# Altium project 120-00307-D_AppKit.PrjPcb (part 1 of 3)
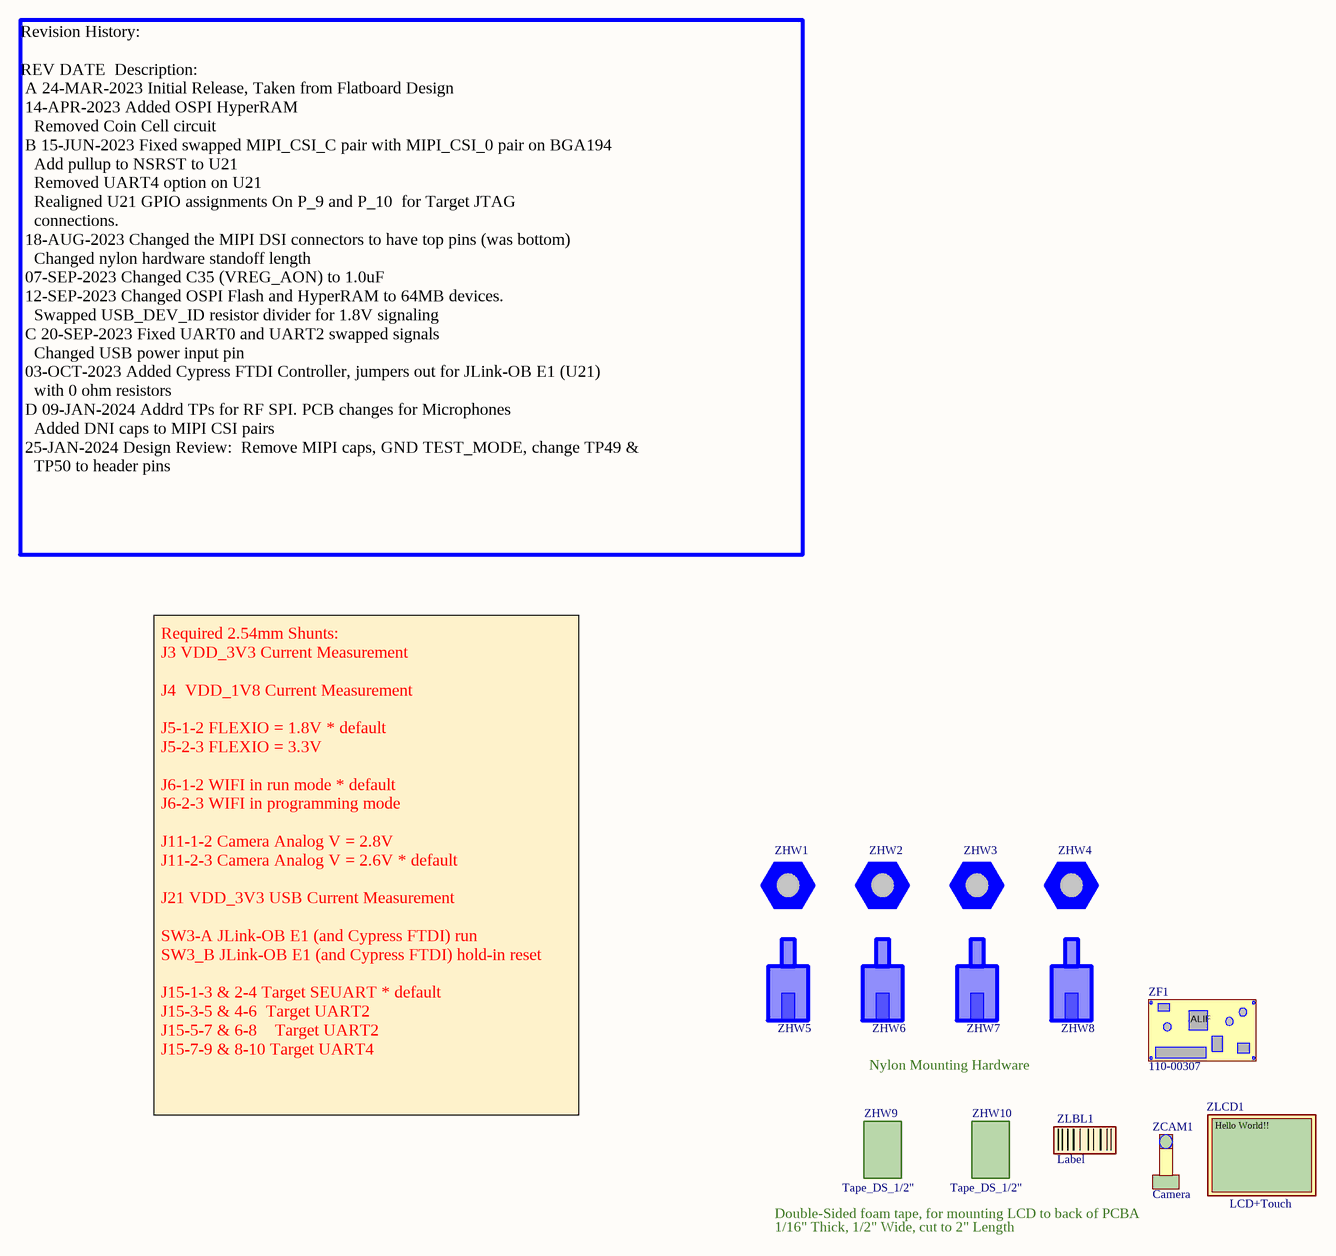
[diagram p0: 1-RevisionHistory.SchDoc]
ASSY_DWG_NO: 120-00307-D; CAGE_CODE: none; CheckedBy: n/a; CHK_APP_DATE: 1/9/24; DOC_NO_ASSY_DWG: 120-00307; DOC_NO_BOM: 250-00307; DOC_NO_FAB_DWG: 210-00307; DOC_NO_SCH_DWG: 220-00307; DOC_REV: D; DrawnBy: K Braun; DSN_APP_DATE: 09-JAN-24; ENG_APP_DATE: 01/09/24; Engineer: K Braun; Fab_DWG_NO: 110-00307; Name-Company: ALIF SEMICONDUCTOR; No-Fab: 110-00307; No-Rev: C; PCB_DWG_NO: 110-00307-D; PROJECT: 00307; Revision: D; SheetTotal: 12; title: APP KIT BOARD
14 sheets, 435 parts. Net scope: flat (ports and power ports of the same name join across sheets).
Board file: 120-00307-D_AppKit.PcbDoc
Sheets:
  1-RevisionHistory.SchDoc
  2-PowerInput.SchDoc
  3-CPUPower.SchDoc
  4-CPUMipiXoMemory.SchDoc
  5-WiFi.SchDoc
  6-GPIOTranslate.SchDoc
  7-CODEC.SchDoc
  8-Sensors.SchDoc
  9-MIPI_CSI.SchDoc
  10-MIPI_DSI.SchDoc
  11-CPU_GPIO.SchDoc
  12-JLINK_1.SchDoc
  13-JLINK_2.SchDoc
  14-CypressSEUART.SchDoc

## Sheet 1-RevisionHistory.SchDoc: APP KIT BOARD
size 431 x 279 mm; Organization: ORGANIZATION; Address1: ADDRESS 1; Address2: ADDRESS 2; Address3: ADDRESS 3; Address4: ADDRESS 4; DocumentNumber: 1; Revision: -; SheetNumber: 1; SheetTotal: 14; ENG_APP_DATE: --/--/--; DSN_APP_DATE: --/--/--; CHK_APP_DATE: --/--/--

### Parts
ZCAM1  Camera  (mechanical)
ZF1  110-00307  (mechanical)
ZHW1  #4-40  (value not drawn)  (mechanical)
ZHW2  #4-40  (value not drawn)  (mechanical)
ZHW3  #4-40  (value not drawn)  (mechanical)
ZHW4  #4-40  (value not drawn)  (mechanical)
ZHW5  #4-40 1/4"  (value not drawn)  (mechanical)
ZHW6  #4-40 1/4"  (value not drawn)  (mechanical)
ZHW7  #4-40 1/4"  (value not drawn)  (mechanical)
ZHW8  #4-40 1/4"  (value not drawn)  (mechanical)
ZHW9  Tape_DS_1/2"  (mechanical)
ZHW10  Tape_DS_1/2"  (mechanical)
ZLBL1  Label  (mechanical)
ZLCD1  LCD+Touch  (mechanical)

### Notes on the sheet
- Revision History:
  REV	DATE		Description:
  A	24-MAR-2023	Initial Release, Taken from Flatboard Design
  14-APR-2023	Added OSPI HyperRAM
  Removed Coin Cell circuit
  B	15-JUN-2023	Fixed swapped MIPI_CSI_C pair with MIPI_CSI_0 pair on BGA194
  Add pullup to NSRST to U21
  Removed UART4 option on U21
  Realigned U21 GPIO assignments On P_9 and P_10  for Target JTAG
  connections.
  18-AUG-2023	Changed the MIPI DSI connectors to have top pins (was bottom)
  Changed nylon hardware standoff length
  07-SEP-2023	Changed C35 (VREG_AON) to 1.0uF
  12-SEP-2023	Changed OSPI Flash and HyperRAM to 64MB devices.
  Swapped USB_DEV_ID resistor divider for 1.8V signaling
  C	20-SEP-2023	Fixed UART0 and UART2 swapped signals
  Changed USB power input pin
  03-OCT-2023	Added Cypress FTDI Controller, jumpers out for JLink-OB E1 (U21)
  with 0 ohm resistors
  D	09-JAN-2024	Addrd TPs for RF SPI. PCB changes for Microphones
  Added DNI caps to MIPI CSI pairs
  25-JAN-2024	Design Review:  Remove MIPI caps, GND TEST_MODE, change TP49 &
  TP50 to header pins
- Required 2.54mm Shunts:
  J3	VDD_3V3 Current Measurement
  J4 	VDD_1V8 Current Measurement
  J5-1-2	FLEXIO = 1.8V * default
  J5-2-3	FLEXIO = 3.3V
  J6-1-2	WIFI in run mode * default
  J6-2-3	WIFI in programming mode
  J11-1-2	Camera Analog V = 2.8V
  J11-2-3	Camera Analog V = 2.6V * default
  J21	VDD_3V3 USB Current Measurement
  SW3-A	JLink-OB E1 (and Cypress FTDI) run
  SW3_B	JLink-OB E1 (and Cypress FTDI) hold-in reset
  J15-1-3 & 2-4	Target SEUART * default
  J15-3-5 & 4-6 	Target UART2
  J15-5-7 & 6-8   	Target UART2
  J15-7-9 & 8-10	Target UART4
- Nylon Mounting Hardware
- Double-Sided foam tape, for mounting LCD to back of PCBA
- 1/16" Thick, 1/2" Wide, cut to 2" Length

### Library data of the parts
ZCAM1 = MOD_CAM: Module, Camera, 2 Lane MIPI; Manufacturer 1: AppleTec; Manufacturer Part Number 1: AP-VISION-ARX3A0-55-C
ZF1 = PCB_FAB: Printed Circuit Board  Fabrication; Manufacturer 1: Alif Semi; Manufacturer Part Number 1: 110-00307-D
ZHW1-ZHW4 = HW_NUT: Hardware, Standoff, Hex Female-Female, #4-40 x 1/4" H, 1/4" Dia, Nylon; Manufacturer 1: Essentra Comp; Manufacturer Part Number 1: 14HTSP001
ZHW5-ZHW8 = HW_STANDOFF_MF: Hardware, Standoff, Hex Male-Female, #4-40 x 5/8" H, 1/4" Dia, Nylon; Manufacturer 1: Keystone; Manufacturer Part Number 1: 4803
ZHW9 ZHW10 = HW_TAPE: Hardware, Tape, 2-sided Foam, 1/2 inch, 1/16 inch thick - Cut to 2 inch length; Manufacturer 1: 3M; Manufacturer Part Number 1: 7010379962
ZLBL1 = MOD_LABEL_GENERIC: Label, UPC, Agency and Lot Num, AppKit; Manufacturer 1: Alif; Manufacturer Part Number 1: -need a p/n-
ZLCD1 = MOD_LCD: Module, LCD, 2 Lane MIPI, 4.3 inch, 480x800,  w/ Touch Panel; Manufacturer 1: FocusLCD; Manufacturer Part Number 1: E43GB-I-MW405-C

## Sheet 2-PowerInput.SchDoc: APP KIT BOARD
size 431 x 279 mm; Organization: ORGANIZATION; Address1: ADDRESS 1; Address2: ADDRESS 2; Address3: ADDRESS 3; Address4: ADDRESS 4; DocumentNumber: 2; Revision: -; SheetNumber: 2; SheetTotal: 14; ENG_APP_DATE: --/--/--; DSN_APP_DATE: --/--/--; CHK_APP_DATE: --/--/--
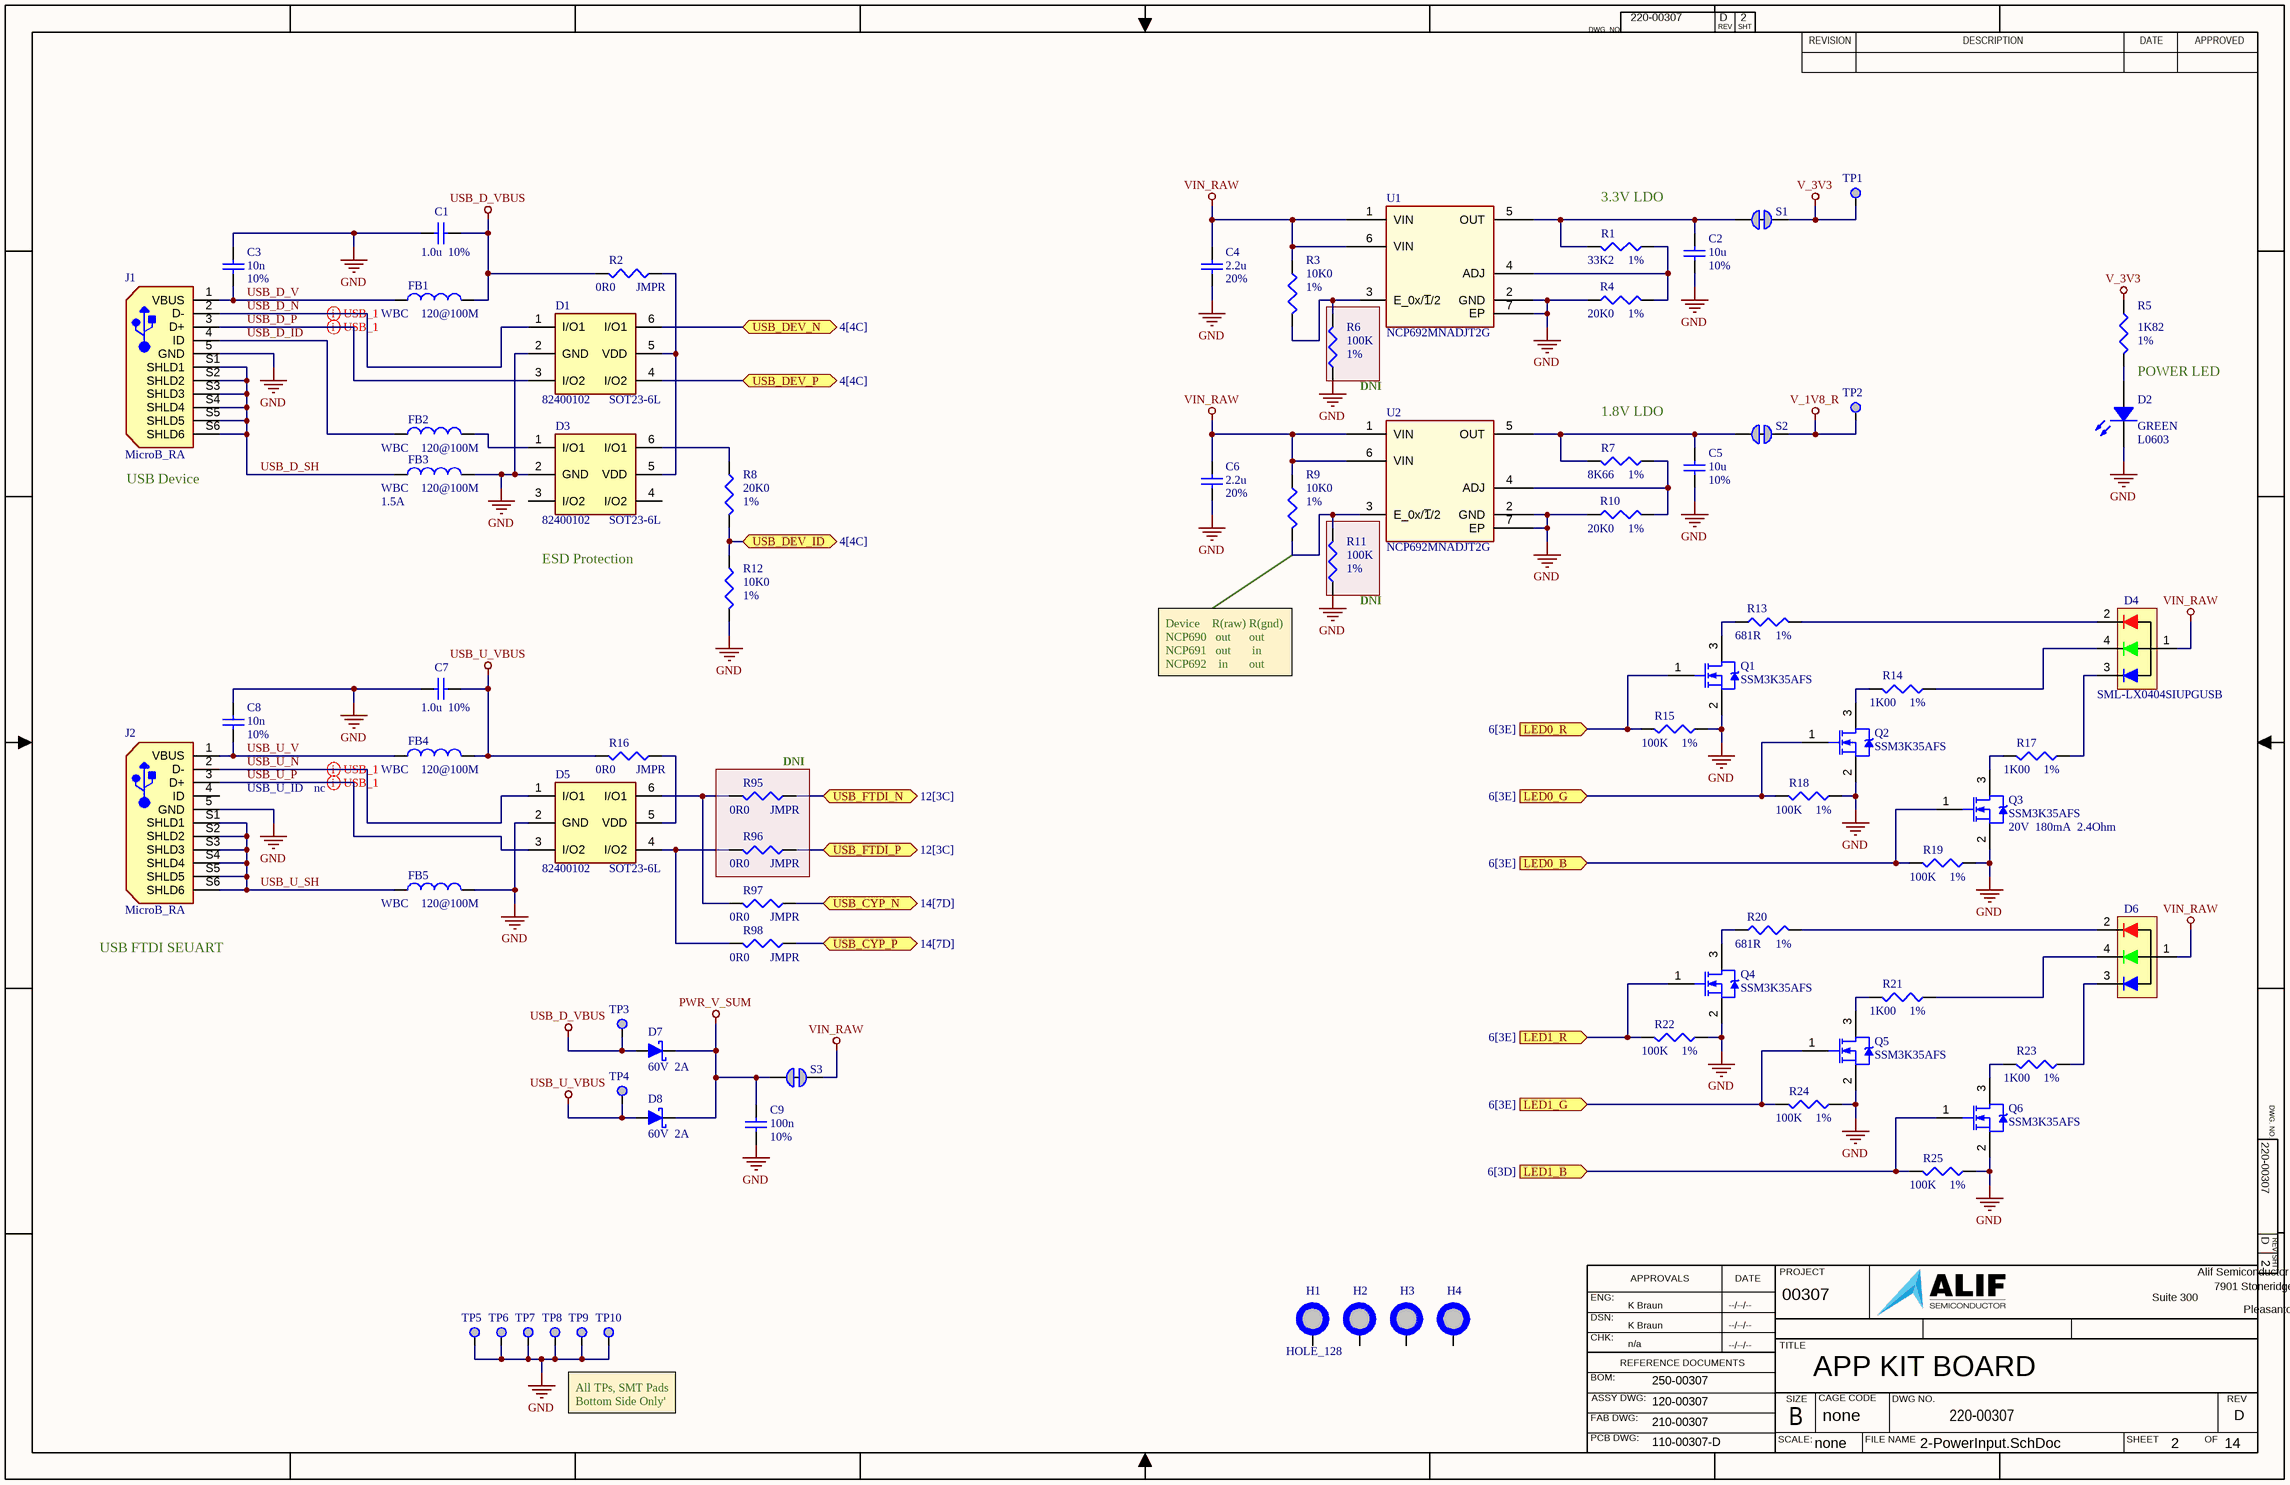
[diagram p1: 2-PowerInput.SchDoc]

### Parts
C1  value 1.0u  Tolerance: 10%  [CAPC0402-01]  (hidden comment: Cap)
C2  value 10u  Tolerance: 10%  [CAPC0402-01]  (hidden comment: Cap)
C3  value 10n  Tolerance: 10%  [CAPC0402-01]  (hidden comment: Cap)
C4  value 2.2u  Tolerance: 20%  [CAPC0402-01]  (hidden comment: Cap_225M25VX5R0402_1)
C5  value 10u  Tolerance: 10%  [CAPC0402-01]  (hidden comment: Cap)
C6  value 2.2u  Tolerance: 20%  [CAPC0402-01]  (hidden comment: Cap_225M25VX5R0402_1)
C7  value 1.0u  Tolerance: 10%  [CAPC0402-01]  (hidden comment: Cap)
C8  value 10n  Tolerance: 10%  [CAPC0402-01]  (hidden comment: Cap)
C9  value 100n  Tolerance: 10%  [CAPC0402-01]  (hidden comment: Cap)
D1  Size: SOT23-6L  [WE-TVS_SOT23-6L]  (hidden comment: TVS 5V 2pF)
D2  value GREEN  PackageReference: L0603  [LED_0603-GRN_AK]  (hidden comment: D LED2)
D3  Size: SOT23-6L  [WE-TVS_SOT23-6L]  (hidden comment: TVS 5V 2pF)
D4  SML-LX0404SIUPGUSB  [LED_SML-LX0404_LUM]
D5  Size: SOT23-6L  [WE-TVS_SOT23-6L]  (hidden comment: TVS 5V 2pF)
D6  SML-LX0404SIUPGUSB  [LED_SML-LX0404_LUM]  (value not drawn)
D7  value 60V  2A  [SOD123F_NXP]  (hidden comment: D Schottky)
D8  value 60V  2A  [SOD123F_NXP]  (hidden comment: D Schottky)
FB1  value WBC  Impedance: 120@100M  [FB_0402]  (hidden comment: Inductor)
FB2  value WBC  Impedance: 120@100M  [FB_0402]  (hidden comment: Inductor)
FB3  value WBC  Impedance: 120@100M  RMS_Current: 1.5A  [FB_0402]  (hidden comment: Inductor)
FB4  value WBC  Impedance: 120@100M  [FB_0402]  (hidden comment: Inductor)
FB5  value WBC  Impedance: 120@100M  [FB_0402]  (hidden comment: Inductor)
H1  HOLE_128  [Hole_#4]  (no BOM)
H2  HOLE_128  [Hole_#4]  (value not drawn)  (no BOM)
H3  HOLE_128  [Hole_#4]  (value not drawn)  (no BOM)
H4  HOLE_128  [Hole_#4]  (value not drawn)  (no BOM)
J1  value MicroB_RA  [AMPHENOL_10118194-0001LF]  (hidden comment: Conn_USB_MicroB_Rt_Angle)
J2  value MicroB_RA  [AMPHENOL_10118194-0001LF]  (hidden comment: Conn_USB_MicroB_Rt_Angle)
Q1  Manufacturer Part Number 1: SSM3K35AFS  [SC75_SSM_TOS-L]  (hidden comment: NMOS-2_SOT)
Q2  Manufacturer Part Number 1: SSM3K35AFS  [SC75_SSM_TOS-L]  (hidden comment: NMOS-2_SOT)
Q3  value 20V  180mA  2.4Ohm  Manufacturer Part Number 1: SSM3K35AFS  [SC75_SSM_TOS-L]  (hidden comment: NMOS-2_SOT)
Q4  Manufacturer Part Number 1: SSM3K35AFS  [SC75_SSM_TOS-L]  (hidden comment: NMOS-2_SOT)
Q5  Manufacturer Part Number 1: SSM3K35AFS  [SC75_SSM_TOS-L]  (hidden comment: NMOS-2_SOT)
Q6  Manufacturer Part Number 1: SSM3K35AFS  [SC75_SSM_TOS-L]  (hidden comment: NMOS-2_SOT)
R1  value 33K2  Tolerance: 1%  [RESC0402-01]  (hidden comment: Res3)
R2  value 0R0  Tolerance: JMPR  [RESC0402-01]  (hidden comment: Res3)
R3  value 10K0  Tolerance: 1%  [RESC0402-01]  (hidden comment: Res3)
R4  value 20K0  Tolerance: 1%  [RESC0402-01]  (hidden comment: Res3)
R5  value 1K82  Tolerance: 1%  [RESC0402-01]  (hidden comment: Res3)
R6  value 100K  Tolerance: 1%  [RESC0402-01]  (hidden comment: Res3)
R7  value 8K66  Tolerance: 1%  [RESC0402-01]  (hidden comment: Res3)
R8  value 20K0  Tolerance: 1%  [RESC0402-01]  (hidden comment: Res3)
R9  value 10K0  Tolerance: 1%  [RESC0402-01]  (hidden comment: Res3)
R10  value 20K0  Tolerance: 1%  [RESC0402-01]  (hidden comment: Res3)
R11  value 100K  Tolerance: 1%  [RESC0402-01]  (hidden comment: Res3)
R12  value 10K0  Tolerance: 1%  [RESC0402-01]  (hidden comment: Res3)
R13  value 681R  Tolerance: 1%  [RESC0402-01]  (hidden comment: Res3)
R14  value 1K00  Tolerance: 1%  [RESC0402-01]  (hidden comment: Res3)
R15  value 100K  Tolerance: 1%  [RESC0402-01]  (hidden comment: Res3)
R16  value 0R0  Tolerance: JMPR  [RESC0402-01]  (hidden comment: Res3)
R17  value 1K00  Tolerance: 1%  [RESC0402-01]  (hidden comment: Res3)
R18  value 100K  Tolerance: 1%  [RESC0402-01]  (hidden comment: Res3)
R19  value 100K  Tolerance: 1%  [RESC0402-01]  (hidden comment: Res3)
R20  value 681R  Tolerance: 1%  [RESC0402-01]  (hidden comment: Res3)
R21  value 1K00  Tolerance: 1%  [RESC0402-01]  (hidden comment: Res3)
R22  value 100K  Tolerance: 1%  [RESC0402-01]  (hidden comment: Res3)
R23  value 1K00  Tolerance: 1%  [RESC0402-01]  (hidden comment: Res3)
R24  value 100K  Tolerance: 1%  [RESC0402-01]  (hidden comment: Res3)
R25  value 100K  Tolerance: 1%  [RESC0402-01]  (hidden comment: Res3)
R95  value 0R0  Tolerance: JMPR  [RESC0402-01]  (hidden comment: Res3)
R96  value 0R0  Tolerance: JMPR  [RESC0402-01]  (hidden comment: Res3)
R97  value 0R0  Tolerance: JMPR  [RESC0402-01]  (hidden comment: Res3)
R98  value 0R0  Tolerance: JMPR  [RESC0402-01]  (hidden comment: Res3)
S1  SolderJumperShorted_Small  [Solderbridge_Shorted]  (value not drawn)  (net tie, no BOM)
S2  SolderJumperShorted_Small  [Solderbridge_Shorted]  (value not drawn)  (net tie, no BOM)
S3  SolderJumperShorted_Small  [Solderbridge_Shorted]  (value not drawn)  (net tie, no BOM)
TP1  TP_SMPAD  [TP_30_RND]  (value not drawn)  (no BOM)
TP2  TP_SMPAD  [TP_30_RND]  (value not drawn)  (no BOM)
TP3  TP_SMPAD  [TP_30_RND]  (value not drawn)  (no BOM)
TP4  TP_SMPAD  [TP_30_RND]  (value not drawn)  (no BOM)
TP5  TP_SMPAD  [TP_30_RND]  (value not drawn)  (no BOM)
TP6  TP_SMPAD  [TP_30_RND]  (value not drawn)  (no BOM)
TP7  TP_SMPAD  [TP_30_RND]  (value not drawn)  (no BOM)
TP8  TP_SMPAD  [TP_30_RND]  (value not drawn)  (no BOM)
TP9  TP_SMPAD  [TP_30_RND]  (value not drawn)  (no BOM)
TP10  TP_SMPAD  [TP_30_RND]  (value not drawn)  (no BOM)
U1  NCP692MNADJT2G  [DFN6_3X3_ONS]
U2  NCP692MNADJT2G  [DFN6_3X3_ONS]

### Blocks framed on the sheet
DNI: R95 R96

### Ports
LED0_B (in, see 6[3E]), LED0_G (in, see 6[3E]), LED0_R (in, see 6[3E]), LED1_B (in, see 6[3D]), LED1_G (in, see 6[3E]), LED1_R (in, see 6[3E]), USB_CYP_N (bidir, see 14[7D]), USB_CYP_P (bidir, see 14[7D]), USB_DEV_ID (bidir, see 4[4C]), USB_DEV_N (bidir, see 4[4C]), USB_DEV_P (bidir, see 4[4C]), USB_FTDI_N (bidir, see 12[3C]), USB_FTDI_P (bidir, see 12[3C])

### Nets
GND: C1.2 C2.1 C3.2 C4.1 C5.1 C6.1 C7.2 C8.2 C9.1 D1.2(GND) D2.K D3.2(GND) D5.2(GND) FB3.2 FB5.2 J1.5(GND) J2.5(GND) Q1.2(S) Q2.2(S) Q3.2(S) Q4.2(S) Q5.2(S) Q6.2(S) R4.1 R6.1 R10.1 R11.1 R12.2 R15.1 R18.1 R19.1 R22.1 R24.1 R25.1 TP5.1 TP6.1 TP7.1 TP8.1 TP9.1 TP10.1 U1.2(GND) U1.7(EP) U2.2(GND) U2.7(EP)
PWR_V_SUM: C9.2 D7.1(K) D8.1(K) S3.1
USB_D_VBUS: C1.1 D7.2(A) FB1.2 R2.2 TP3.1
USB_U_VBUS: C7.1 D8.2(A) FB4.2 R16.2 TP4.1
V_1V8_R: S2.2 TP2.1
V_3V3: R5.1 S1.2 TP1.1
VIN_RAW: C4.2 C6.2 D4.1(A) D6.1(A) R3.1 R9.1 S3.2 U1.1(VIN) U1.6(VIN) U2.1(VIN) U2.6(VIN)
P6_2: Q4.1(G) R22.2 ; port LED1_R
P6_5: Q5.1(G) R24.2 ; port LED1_G
P6_6: Q6.1(G) R25.2 ; port LED1_B
P7_4: Q2.1(G) R18.2 ; port LED0_G
P12_0: Q3.1(G) R19.2 ; port LED0_B
P12_3: Q1.1(G) R15.2 ; port LED0_R
USB_CYP_N: R97.1 ; port USB_CYP_N
USB_CYP_P: R98.1 ; port USB_CYP_P
USB_D_ID: FB2.1 J1.4(ID)
USB_D_N: D1.1(I/O1) J1.2(D-)
USB_D_P: D1.3(I/O2) J1.3(D+)
USB_D_SH: FB3.1 J1.S1(SHLD1) J1.S2(SHLD2) J1.S3(SHLD3) J1.S4(SHLD4) J1.S5(SHLD5) J1.S6(SHLD6)
USB_D_V: C3.1 FB1.1 J1.1(VBUS)
USB_DEV_N: D1.6(I/O1) ; port USB_DEV_N
USB_DEV_P: D1.4(I/O2) ; port USB_DEV_P
USB_FTDI_N: R95.1 ; port USB_FTDI_N
USB_FTDI_P: R96.1 ; port USB_FTDI_P
USB_ID: R8.2 R12.1 ; port USB_DEV_ID
USB_U_N: D5.1(I/O1) J2.2(D-)
USB_U_P: D5.3(I/O2) J2.3(D+)
USB_U_SH: FB5.1 J2.S1(SHLD1) J2.S2(SHLD2) J2.S3(SHLD3) J2.S4(SHLD4) J2.S5(SHLD5) J2.S6(SHLD6)
USB_U_V: C8.1 FB4.1 J2.1(VBUS)
NetC2_2: C2.2 R1.2 S1.1 U1.5(OUT)
NetC5_2: C5.2 R7.2 S2.1 U2.5(OUT)
NetD1_5: D1.5(VDD) D3.5(VDD) R2.1
NetD2_A: D2.A R5.2
NetD3_1: D3.1(I/O1) FB2.2
NetD3_6: D3.6(I/O1) R8.1
NetD4_2: D4.2(RK) R13.2
NetD4_3: D4.3(BK) R17.1
NetD4_4: D4.4(GK) R14.1
NetD5_4: D5.4(I/O2) R96.2 R98.2
NetD5_5: D5.5(VDD) R16.1
NetD5_6: D5.6(I/O1) R95.2 R97.2
NetD6_2: D6.2(RK) R20.2
NetD6_3: D6.3(BK) R23.1
NetD6_4: D6.4(GK) R21.1
NetQ1_3: Q1.3(D) R13.1
NetQ2_3: Q2.3(D) R14.2
NetQ3_3: Q3.3(D) R17.2
NetQ4_3: Q4.3(D) R20.1
NetQ5_3: Q5.3(D) R21.2
NetQ6_3: Q6.3(D) R23.2
NetR1_1: R1.1 R4.2 U1.4(ADJ)
NetR3_2: R3.2 R6.2 U1.3(E_0x/~{1}/2)
NetR7_1: R7.1 R10.2 U2.4(ADJ)
NetR9_2: R9.2 R11.2 U2.3(E_0x/~{1}/2)

Not connected (* = marked no-connect by the designer): D3 3(I/O2) 4(I/O2); H1 1; H2 1; H3 1; H4 1; J2 4(ID)

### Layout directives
differential pair; differential pair class USB_D: USB_D_N, USB_D_P
differential pair; differential pair class USB_U: USB_U_N, USB_U_P

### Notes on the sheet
- 3.3V LDO
- DNI
- 1.8V LDO
- (near R5) POWER LED
- (near J1) USB Device
- (near D3) ESD Protection
- (near R11) DNI
- (near R11) Device    R(raw) R(gnd)
  NCP690   out      out
  NCP691   out       in
  NCP692    in       out
- USB_U_ID
- nc
- (near J2) USB FTDI SEUART
- All TPs, SMT Pads
  Bottom Side Only'

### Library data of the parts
C1 C7 = Cap: Cap,1.0uF,20%,25V,X5R,0402; Manufacturer 1: TDK; Manufacturer Part Number 1: CGB2A1X5R1E105K033BC; PCB_Footprint: CC0402
C2 C5 = Cap: Cap,10uF,20%,10V,X5R,0402; Manufacturer 1: AVX; Manufacturer Part Number 1: 0402ZD106MAT2A; PCB_Footprint: CC0402
C3 C8 = Cap: Cap,10nF,10%,50V,X7R,0402; Manufacturer 1: TDK; Manufacturer Part Number 1: CGA2B3X7R1H103K050BE; PCB_Footprint: CC0402
C4 C6 = Cap_225M25VX5R0402_1: Cap,2.2uF,20%,25V,X5R,0402; Manufacturer 1: TDK; Manufacturer Part Number 1: C1005X5R1E225M050BC; PCB_Footprint: CC0402
C9 = Cap: Cap,100nF,10%,50V,X7R,0402; Manufacturer 1: TDK; Manufacturer Part Number 1: C1005X7R1H104K050BE; PCB_Footprint: CC0402
D1 D3 D5 = 82400102: Diode,TVS  – High Speed Series, SOT23-6L, 2+1 Channel, 5Vdc, 2pF; Manufacturer: Wurth Elektronik; Manufacturer 1: Wurth; Reverse Peak Pulse Current: 7A; Channel ESD Clamping Voltage: 10V; Channel Reverse Leakage Current: 1uA; ESD Air Discharge Capability: 15kV; ESD Contact Discharge Capability: 8kV; Polarity: Unidirectional; Reverse Breakdown Voltage: 6V
D2 = D LED2: Diode,LED,Green 573nm,300mcd @ 20mA,0603; Manufacturer 1: Wurth; Manufacturer Part Number 1: 150060VS86000
D4 D6 = D LED_RGB_CA_1MMc1MM: Diode,LED,RGB, (@2mA) -> R=10mcd & 1.75V, G = 50mcd & 2.75V, B = 20mcd & 2.95V, 0404(1mm x 1mm); Manufacturer 1: Lumex
D7 D8 = D Schottky: Diode,Schottky,2A,60V, <50uA@60V,SOD123F; Manufacturer 1: OnSemi; Manufacturer Part Number 1: SS26FL
FB1-FB5 = Inductor: Ind,WidebandChoke,1.5A,120ohm@100MHz,95mOhm,0402; Manufacturer 1: MuRata; Manufacturer Part Number 1: BLM15EG121SN1D; Code_IEC: 1005
H1-H4 = HOLE_128: Hole, #4,--not a BOM item--; PCB_Footprint: TP_PAD1
J1 J2 = Conn_USB-5-6SHLD: Conn,Micro USB B Type Receptacle,Right Angle; Manufacturer: Amphenol FCI; Manufacturer Part Number 1: 10118194-0001LF; Pitch: 0.65mm; Gender: RCP; Rad Hard: No
Q1 Q2 Q4-Q6 = NMOS-2_SOT: MOSFET,N-CH,20V,250mA,1.1Ohm,SOT-23; Manufacturer 1: Toshiba; Note: Pin 2 is electrically connected to pin 4.; Value: 20V  180mA  2.4Ohm
Q3 = NMOS-2_SOT: MOSFET,N-CH,20V,250mA,1.1Ohm,SOT-23; Manufacturer 1: Toshiba; Note: Pin 2 is electrically connected to pin 4.
R1 = Res3: Res,33K2,1%,100ppm,0402; Manufacturer 1: Stackpol; Manufacturer Part Number 1: RMCF0402FT33K2; Wattage: 63mW
R2 R16 R97 R98 = Res3: Res,0R ohm,Jumper,0402; Manufacturer 1: Stackpol; Manufacturer Part Number 1: RMCF0402ZT0R00; Wattage: 63mW
R3 R9 R12 = Res3: Res,10K0,1%,100ppm,0402; Manufacturer 1: Stackpol; Manufacturer Part Number 1: RMCF0402FT10K0; Wattage: 63mW
R4 R8 R10 = Res3: Res,20K0,1%,100ppm,0402; Manufacturer 1: Stackpol; Manufacturer Part Number 1: RMCF0402FT20K0; Wattage: 63mW
R5 = Res3: Res,1K82,1%,100ppm,0402; Manufacturer 1: Stackpol; Manufacturer Part Number 1: RMCF0402FT1K82; Wattage: 63mW
R6 R11 = Res3: DNI,Res,100K,1%,100ppm,0402; Manufacturer 1: Stackpol; Manufacturer Part Number 1: RMCF0402FT100K; Wattage: 63mW
R7 = Res3: Res,8K66,1%,100ppm,0402; Manufacturer 1: Stackpol; Manufacturer Part Number 1: RMCF0402FT8K66; Wattage: 63mW
R13 R20 = Res3: Res,681R,1%,100ppm,0402; Manufacturer 1: Stackpol; Manufacturer Part Number 1: RMCF0402FT681R; Wattage: 63mW
R14 R17 R21 R23 = Res3: Res,1K00,1%,100ppm,0402; Manufacturer 1: Stackpol; Manufacturer Part Number 1: RMCF0402FT1K; Wattage: 63mW
R15 R18 R19 R22 R24 R25 = Res3: Res,100K,1%,100ppm,0402; Manufacturer 1: Stackpol; Manufacturer Part Number 1: RMCF0402FT100K; Wattage: 63mW
R95 R96 = Res3: DNI,Res,0R ohm,Jumper,0402; Manufacturer 1: Stackpol; Manufacturer Part Number 1: RMCF0402ZT0R00; Wattage: 63mW
S1-S3 = SolderJumperShorted_Small: DNI,Solderable Jumper,Shorted; Wattage: 63mW; PCB_Footprint: SSHORTED
TP1-TP10 = TP_SMPAD: Test Point, SMT Pad,--not a BOM item--; PCB_Footprint: TP_PAD1
U1 U2 = IC_LDO_NCP690MNADJT2G: IC, LDO,Adj 1.25V - 5.5V,1.0A,+ Enable,DFN6; Manufacturer 1: OnSemi

## Sheet 3-CPUPower.SchDoc: APP KIT BOARD
size 431 x 279 mm; Organization: ORGANIZATION; Address1: ADDRESS 1; Address2: ADDRESS 2; Address3: ADDRESS 3; Address4: ADDRESS 4; DocumentNumber: 3; Revision: -; SheetNumber: 3; SheetTotal: 14; ENG_APP_DATE: --/--/--; DSN_APP_DATE: --/--/--; CHK_APP_DATE: --/--/--
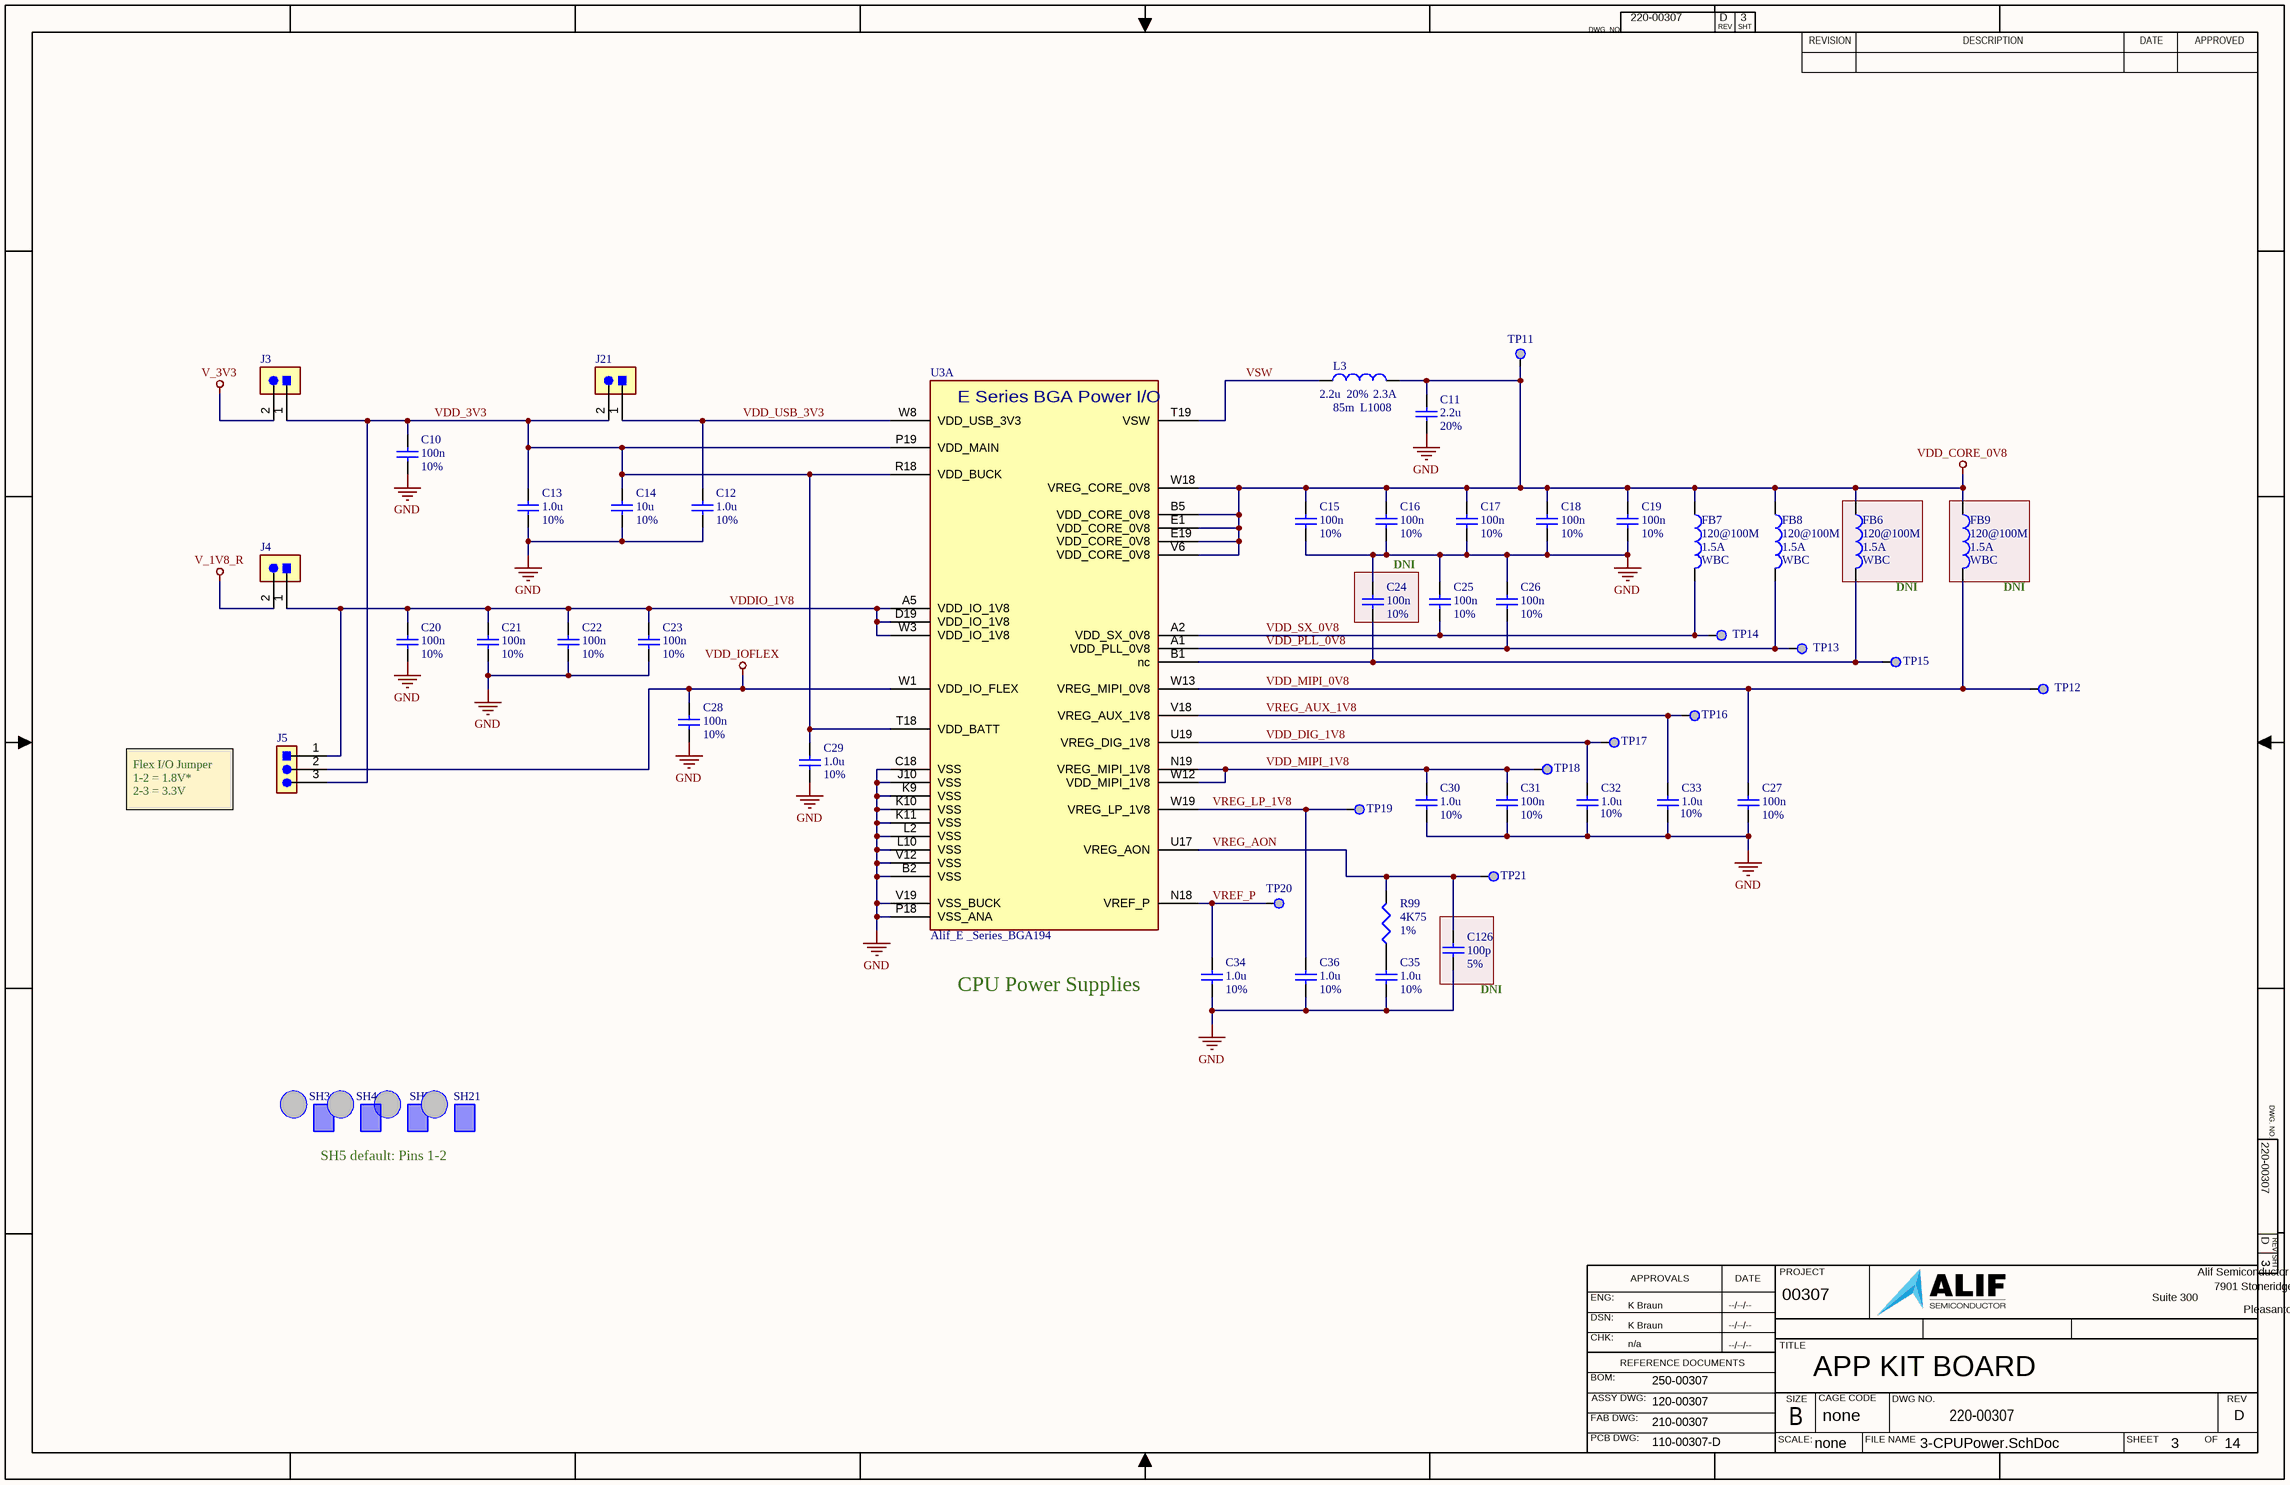
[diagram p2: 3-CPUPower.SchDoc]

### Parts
C10  value 100n  Tolerance: 10%  [CAPC0402-01]  (hidden comment: Cap)
C11  value 2.2u  Tolerance: 20%  [CAPC0402-01]  (hidden comment: Cap_225M25VX5R0402_1)
C12  value 1.0u  Tolerance: 10%  [CAPC0402-01]  (hidden comment: Cap)
C13  value 1.0u  Tolerance: 10%  [CAPC0402-01]  (hidden comment: Cap)
C14  value 10u  Tolerance: 10%  [CAPC0402-01]  (hidden comment: Cap)
C15  value 100n  Tolerance: 10%  [CAPC0402-01]  (hidden comment: Cap)
C16  value 100n  Tolerance: 10%  [CAPC0402-01]  (hidden comment: Cap)
C17  value 100n  Tolerance: 10%  [CAPC0402-01]  (hidden comment: Cap)
C18  value 100n  Tolerance: 10%  [CAPC0402-01]  (hidden comment: Cap)
C19  value 100n  Tolerance: 10%  [CAPC0402-01]  (hidden comment: Cap)
C20  value 100n  Tolerance: 10%  [CAPC0402-01]  (hidden comment: Cap)
C21  value 100n  Tolerance: 10%  [CAPC0402-01]  (hidden comment: Cap)
C22  value 100n  Tolerance: 10%  [CAPC0402-01]  (hidden comment: Cap)
C23  value 100n  Tolerance: 10%  [CAPC0402-01]  (hidden comment: Cap)
C24  value 100n  Tolerance: 10%  [CAPC0402-01]  (hidden comment: Cap)
C25  value 100n  Tolerance: 10%  [CAPC0402-01]  (hidden comment: Cap)
C26  value 100n  Tolerance: 10%  [CAPC0402-01]  (hidden comment: Cap)
C27  value 100n  Tolerance: 10%  [CAPC0402-01]  (hidden comment: Cap)
C28  value 100n  Tolerance: 10%  [CAPC0402-01]  (hidden comment: Cap)
C29  value 1.0u  Tolerance: 10%  [CAPC0402-01]  (hidden comment: Cap)
C30  value 1.0u  Tolerance: 10%  [CAPC0402-01]  (hidden comment: Cap)
C31  value 100n  Tolerance: 10%  [CAPC0402-01]  (hidden comment: Cap)
C32  value 1.0u  Tolerance: 10%  [CAPC0402-01]  (hidden comment: Cap)
C33  value 1.0u  Tolerance: 10%  [CAPC0402-01]  (hidden comment: Cap)
C34  value 1.0u  Tolerance: 10%  [CAPC0402-01]  (hidden comment: Cap)
C35  value 1.0u  Tolerance: 10%  [CAPC0402-01]  (hidden comment: Cap)
C36  value 1.0u  Tolerance: 10%  [CAPC0402-01]  (hidden comment: Cap)
C126  value 100p  Tolerance: 5%  [CAPC0402-01]  (hidden comment: Cap)
FB6  value WBC  Impedance: 120@100M  RMS_Current: 1.5A  [FB_0402]  (hidden comment: Inductor)
FB7  value WBC  Impedance: 120@100M  RMS_Current: 1.5A  [FB_0402]  (hidden comment: Inductor)
FB8  value WBC  Impedance: 120@100M  RMS_Current: 1.5A  [FB_0402]  (hidden comment: Inductor)
FB9  value WBC  Impedance: 120@100M  RMS_Current: 1.5A  [FB_0402]  (hidden comment: Inductor)
J3  TSW-102-07-G-S  [CONN_77311-146-02LF_AMP_HDR_1x2_2.5MM_STRT]  (value not drawn)
J4  TSW-102-07-G-S  [CONN_77311-146-02LF_AMP_HDR_1x2_2.5MM_STRT]  (value not drawn)
J5  TSW-103-07-G-S  [CONN_HDR_1X3_STRT_0.100]  (value not drawn)
J21  TSW-102-07-G-S  [CONN_77311-146-02LF_AMP_HDR_1x2_2.5MM_STRT]  (value not drawn)
L3  value 2.2u  PackageReference: L1008  DCR: 85m  RMS_Current: 2.3A  Tolerance: 20%  [INDC2520X120N]  (hidden comment: Inductor)
R99  value 4K75  Tolerance: 1%  [RESC0402-01]  (hidden comment: Res3)
SH3  Shunt  (value not drawn)  (mechanical)
SH4  Shunt  (value not drawn)  (mechanical)
SH5  Shunt  (value not drawn)  (mechanical)
SH21  Shunt  (value not drawn)  (mechanical)
TP11  TP_SMPAD  [TP_30_RND]  (value not drawn)  (no BOM)
TP12  TP_SMPAD  [TP_30_RND]  (value not drawn)  (no BOM)
TP13  TP_SMPAD  [TP_30_RND]  (value not drawn)  (no BOM)
TP14  TP_SMPAD  [TP_30_RND]  (value not drawn)  (no BOM)
TP15  TP_SMPAD  [TP_30_RND]  (value not drawn)  (no BOM)
TP16  TP_SMPAD  [TP_30_RND]  (value not drawn)  (no BOM)
TP17  TP_SMPAD  [TP_30_RND]  (value not drawn)  (no BOM)
TP18  TP_SMPAD  [TP_30_RND]  (value not drawn)  (no BOM)
TP19  TP_SMPAD  [TP_30_RND]  (value not drawn)  (no BOM)
TP20  TP_SMPAD  [TP_30_RND]  (value not drawn)  (no BOM)
TP21  TP_SMPAD  [TP_30_RND]  (value not drawn)  (no BOM)
U3  Alif_E _Series_BGA194  [BGA194 _CENTERED]  (part A of 4)

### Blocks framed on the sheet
DNI: C24

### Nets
GND: C10.1 C11.1 C12.1 C13.1 C14.1 C15.1 C16.1 C17.1 C18.1 C19.1 C20.1 C21.1 C22.1 C23.1 C24.2 C25.2 C26.2 C27.1 C28.1 C29.1 C30.1 C31.1 C32.1 C33.1 C34.1 C35.1 C36.1 C126.1 U3.B2(VSS) U3.C18(VSS) U3.J10(VSS) U3.K9(VSS) U3.K10(VSS) U3.K11(VSS) U3.L2(VSS) U3.L10(VSS) U3.P18(VSS_ANA) U3.V12(VSS) U3.V19(VSS_BUCK)
V_1V8_R: J4.2
V_3V3: J3.2
VDD_CORE_0V8: C11.2 C15.2 C16.2 C17.2 C18.2 C19.2 FB6.1 FB7.1 FB8.1 FB9.1 L3.2 TP11.1 U3.B5(VDD_CORE_0V8) U3.E1(VDD_CORE_0V8) U3.E19(VDD_CORE_0V8) U3.V6(VDD_CORE_0V8) U3.W18(VREG_CORE_0V8)
VDD_IOFLEX: C28.2 J5.2 U3.W1(VDD_IO_FLEX)
VDD_3V3: C10.2 C13.2 C14.2 C29.2 J3.1 J5.3 J21.2 U3.P19(VDD_MAIN) U3.R18(VDD_BUCK) U3.T18(VDD_BATT)
VDD_DIG_1V8: C32.2 TP17.1 U3.U19(VREG_DIG_1V8)
VDD_MIPI_0V8: C27.2 FB9.2 TP12.1 U3.W13(VREG_MIPI_0V8)
VDD_MIPI_1V8: C30.2 C31.2 TP18.1 U3.N19(VREG_MIPI_1V8) U3.W12(VDD_MIPI_1V8)
VDD_PLL_0V8: C26.1 FB8.2 TP13.1 U3.A1(VDD_PLL_0V8)
VDD_SX_0V8: C25.1 FB7.2 TP14.1 U3.A2(VDD_SX_0V8)
VDD_USB_3V3: C12.2 J21.1 U3.W8(VDD_USB_3V3)
VDDIO_1V8: C20.2 C21.2 C22.2 C23.2 J4.1 J5.1 U3.A5(VDD_IO_1V8) U3.D19(VDD_IO_1V8) U3.W3(VDD_IO_1V8)
VREF_P: C34.2 TP20.1 U3.N18(VREF_P)
VREG_AON: C126.2 R99.2 TP21.1 U3.U17(VREG_AON)
VREG_AUX_1V8: C33.2 TP16.1 U3.V18(VREG_AUX_1V8)
VREG_LP_1V8: C36.2 TP19.1 U3.W19(VREG_LP_1V8)
VSW: L3.1 U3.T19(VSW)
NetC24_1: C24.1 FB6.2 TP15.1 U3.B1(nc)
NetC35_2: C35.2 R99.1

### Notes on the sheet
- DNI
- (near FB9) DNI
- Flex I/O Jumper
  1-2 = 1.8V*
  2-3 = 3.3V
- CPU Power Supplies
- (near C126) DNI
- SH5 default: Pins 1-2

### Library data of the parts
C10 C15-C23 C25-C28 C31 = Cap: as C9 on sheet 2-PowerInput
C11 = Cap_225M25VX5R0402_1: as C4 on sheet 2-PowerInput
C12 C13 C29 C30 C32-C36 = Cap: as C1 on sheet 2-PowerInput
C14 = Cap: as C2 on sheet 2-PowerInput
C24 = Cap: DNI, Cap,100nF,10%,50V,X7R,0402; Manufacturer 1: TDK; Manufacturer Part Number 1: C1005X7R1H104K050BE; PCB_Footprint: CC0402
C126 = Cap_SMT: DNI,Cap,100pF,5%,50V,C0G,0402; Manufacturer 1: Kemet; Manufacturer Part Number 1: CBR04C101J3GAC; PCB_Footprint: CC0402
FB6 FB9 = Inductor: DNI, Ind,WidebandChoke,1.5A,120ohm@100MHz,95mOhm,0402; Manufacturer 1: MuRata; Manufacturer Part Number 1: BLM15EG121SN1D; Code_IEC: 1005
FB7 FB8 = Inductor: as FB1 on sheet 2-PowerInput
J3 J4 J21 = Hdr_M_1X2_2M54_STRT_UNSHROUD: Hdr, 0.025" SQ Post Header, Through-hole, Vertical, -55 to 125 degC, 2.54 mm Pitch, 2-Pin, Male, RoHS; Manufacturer: Samtec; Manufacturer Part Number 1: TSW-102-07-L-S; Pitch: 2.54 mm
J5 = Hdr_M_1X3_2M54_STRT_UNSHROUD: Hdr, 0.025" SQ Post Header, Through-hole, Vertical, -55 to 125 degC, 2.54 mm Pitch, 3-Pin, Male, RoHS; Manufacturer: Samtec; Manufacturer Part Number 1: TSW-103-07-L-S; Pitch: 2.54 mm
L3 = Inductor: Ind,Unshielded,2.2uH,20%,2.3A,85mOhm,1008(2520); Manufacturer 1: MuRata; Manufacturer Part Number 1: DFE252012F-2R2M=P2; Code_IEC: 2520
R99 = Res3: Res,4K75,1%,100ppm,0402; Manufacturer 1: Stackpol; Manufacturer Part Number 1: RMCF0402FT4K75; Wattage: 63mW
SH3-SH5 SH21 = SHUNT_F_1x2_2.5MM_STRT: Shunt,Female,1x2,2.54mm,Gold,Strt; Manufacturer 1: Samtec; Manufacturer Part Number 1: SNT-100-BK-H
TP11-TP21 = TP_SMPAD: as TP1 on sheet 2-PowerInput
U3 = E7_B0_194BGA: IC,Alif E7 MCU, Rev B silicon, 5.5MB MRAM, 13.5MB SRAM, BGA194; Manufacturer 1: Alif Semi; Manufacturer Part Number 1: AE722F80F55D5LS

## Sheet 4-CPUMipiXoMemory.SchDoc: APP KIT BOARD
size 431 x 279 mm; Organization: ORGANIZATION; Address1: ADDRESS 1; Address2: ADDRESS 2; Address3: ADDRESS 3; Address4: ADDRESS 4; DocumentNumber: 4; Revision: -; SheetNumber: 4; SheetTotal: 14; ENG_APP_DATE: --/--/--; DSN_APP_DATE: --/--/--; CHK_APP_DATE: --/--/--
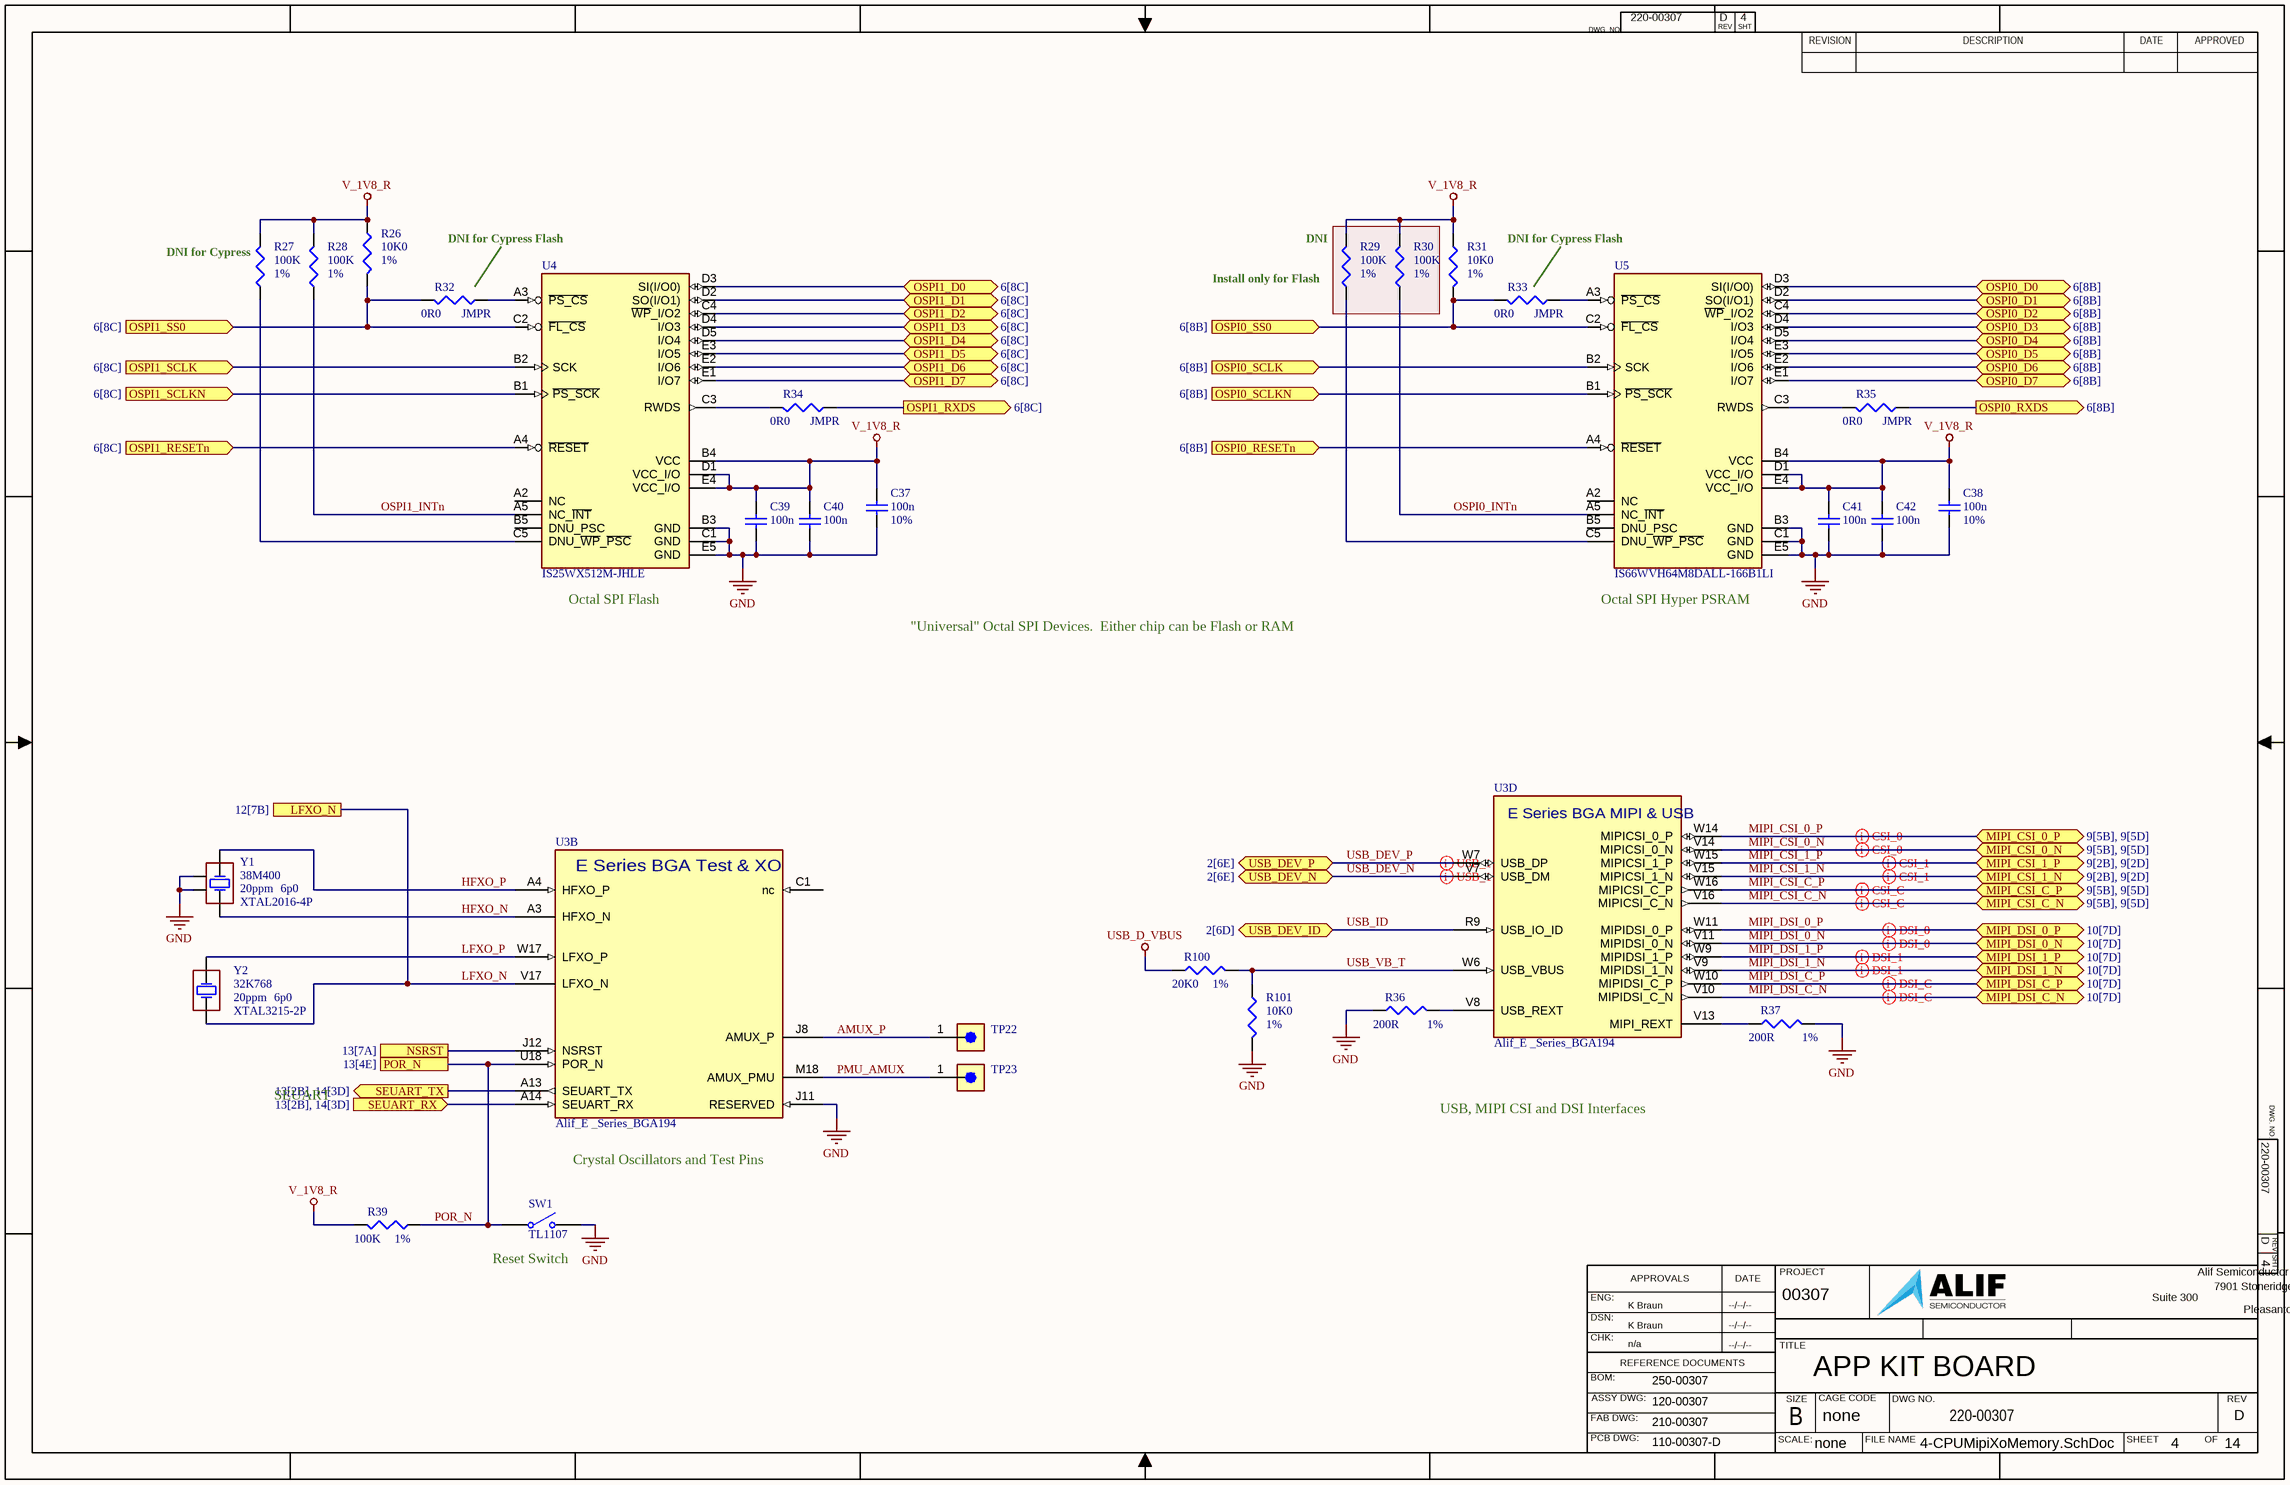
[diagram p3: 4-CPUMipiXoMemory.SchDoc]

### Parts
C37  value 100n  Tolerance: 10%  [CAPC0402-01]  (hidden comment: Cap)
C38  value 100n  Tolerance: 10%  [CAPC0402-01]  (hidden comment: Cap)
C39  value 100n  [CAPC0402-01]  (hidden comment: Cap)
C40  value 100n  [CAPC0402-01]  (hidden comment: Cap)
C41  value 100n  [CAPC0402-01]  (hidden comment: Cap)
C42  value 100n  [CAPC0402-01]  (hidden comment: Cap)
R26  value 10K0  Tolerance: 1%  [RESC0402-01]  (hidden comment: Res3)
R27  value 100K  Tolerance: 1%  [RESC0402-01]  (hidden comment: Res3)
R28  value 100K  Tolerance: 1%  [RESC0402-01]  (hidden comment: Res3)
R29  value 100K  Tolerance: 1%  [RESC0402-01]  (hidden comment: Res3)
R30  value 100K  Tolerance: 1%  [RESC0402-01]  (hidden comment: Res3)
R31  value 10K0  Tolerance: 1%  [RESC0402-01]  (hidden comment: Res3)
R32  value 0R0  Tolerance: JMPR  [RESC0402-01]  (hidden comment: Res3)
R33  value 0R0  Tolerance: JMPR  [RESC0402-01]  (hidden comment: Res3)
R34  value 0R0  Tolerance: JMPR  [RESC0402-01]  (hidden comment: Res3)
R35  value 0R0  Tolerance: JMPR  [RESC0402-01]  (hidden comment: Res3)
R36  value 200R  Tolerance: 1%  [RESC0402-01]  (hidden comment: Res3)
R37  value 200R  Tolerance: 1%  [RESC0402-01]  (hidden comment: Res3)
R39  value 100K  Tolerance: 1%  [RESC0402-01]  (hidden comment: Res3)
R100  value 20K0  Tolerance: 1%  [RESC0402-01]  (hidden comment: Res3)
R101  value 10K0  Tolerance: 1%  [RESC0402-01]  (hidden comment: Res3)
SW1  value TL1107  [SW_1825966-TL1107-1]  (hidden comment: SW-SPST)
TP22  TSW-101-07-G-S  [CONN_77311-146-01LF_AMP_HDR_1X1_2.5MM_STRT_No3D]  (value not drawn)
TP23  TSW-101-07-G-S  [CONN_77311-146-01LF_AMP_HDR_1X1_2.5MM_STRT_No3D]  (value not drawn)
U3  Alif_E _Series_BGA194  [BGA194 _CENTERED]  (parts B,D of 4)
U4  Manufacturer Part Number 1: IS25WX512M-JHLE  [BGA24C100P5X5_800X600X100N]  (hidden comment: IC_OctalSPI_Generic_1)
U5  Manufacturer Part Number 1: IS66WVH64M8DALL-166B1LI  [BGA24C100P5X5_800X600X100N]  (hidden comment: IC_OctalSPI_Generic_1)
Y1  value 38M400  PCB_Footprint: XTAL2016-4P  PPM: 20ppm  Load Cap: 6p0  [OSC_4p_2016_XRCGB38M400F2P00R0]  (hidden comment: Xtal_38M4_20PPM6PF_2016-4P_1)
Y2  value 32K768  PCB_Footprint: XTAL3215-2P  PPM: 20ppm  Load Cap: 6p0  [XTAL_ABS07_ABR-M]  (hidden comment: Xtal_32K768_20PPM6PF_3215-2P_1)

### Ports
LFXO_N (see 12[7B]), MIPI_CSI_0_N (bidir, see 9[5B], 9[5D]), MIPI_CSI_0_P (bidir, see 9[5B], 9[5D]), MIPI_CSI_1_N (bidir, see 9[2B], 9[2D]), MIPI_CSI_1_P (bidir, see 9[2B], 9[2D]), MIPI_CSI_C_N (bidir, see 9[5B], 9[5D]), MIPI_CSI_C_P (bidir, see 9[5B], 9[5D]), MIPI_DSI_0_N (bidir, see 10[7D]), MIPI_DSI_0_P (bidir, see 10[7D]), MIPI_DSI_1_N (bidir, see 10[7D]), MIPI_DSI_1_P (bidir, see 10[7D]), MIPI_DSI_C_N (bidir, see 10[7D]), MIPI_DSI_C_P (bidir, see 10[7D]), NSRST (see 13[7A]), OSPI0_D0 (bidir, see 6[8B]), OSPI0_D1 (bidir, see 6[8B]), OSPI0_D2 (bidir, see 6[8B]), OSPI0_D3 (bidir, see 6[8B]), OSPI0_D4 (bidir, see 6[8B]), OSPI0_D5 (bidir, see 6[8B]), OSPI0_D6 (bidir, see 6[8B]), OSPI0_D7 (bidir, see 6[8B]), OSPI0_RESETn (in, see 6[8B]), OSPI0_RXDS (out, see 6[8B]), OSPI0_SCLK (in, see 6[8B]), OSPI0_SCLKN (in, see 6[8B]), OSPI0_SS0 (in, see 6[8B]), OSPI1_D0 (bidir, see 6[8C]), OSPI1_D1 (bidir, see 6[8C]), OSPI1_D2 (bidir, see 6[8C]), OSPI1_D3 (bidir, see 6[8C]), OSPI1_D4 (bidir, see 6[8C]), OSPI1_D5 (bidir, see 6[8C]), OSPI1_D6 (bidir, see 6[8C]), OSPI1_D7 (bidir, see 6[8C]), OSPI1_RESETn (in, see 6[8C]), OSPI1_RXDS (out, see 6[8C]), OSPI1_SCLK (in, see 6[8C]), OSPI1_SCLKN (in, see 6[8C]), OSPI1_SS0 (in, see 6[8C]), POR_N (see 13[4E]), SEUART_RX (in, see 13[2B], 14[3D]), SEUART_TX (out, see 13[2B], 14[3D]), USB_DEV_ID (bidir, see 2[6D]), USB_DEV_N (bidir, see 2[6E]), USB_DEV_P (bidir, see 2[6E])

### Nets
GND: C37.1 C38.1 C39.1 C40.1 C41.1 C42.1 R36.1 R37.2 R101.2 SW1.2(NO) U3.J11(RESERVED) U4.B3(GND) U4.C1(GND) U4.E5(GND) U5.B3(GND) U5.C1(GND) U5.E5(GND) Y1.2 Y1.4
USB_D_VBUS: R100.1
V_1V8_R: C37.2 C38.2 C39.2 C40.2 C41.2 C42.2 R26.1 R27.2 R28.2 R29.2 R30.2 R31.1 R39.2 U4.B4(VCC) U4.D1(VCC_I/O) U4.E4(VCC_I/O) U5.B4(VCC) U5.D1(VCC_I/O) U5.E4(VCC_I/O)
AMUX_P: TP22.1 U3.J8(AMUX_P)
HFXO_N: U3.A3(HFXO_N) Y1.3(OSC2)
HFXO_P: U3.A4(HFXO_P) Y1.1(OSC1)
LFXO_N: U3.V17(LFXO_N) Y2.1(OSC1) ; port LFXO_N
LFXO_P: U3.W17(LFXO_P) Y2.2(OSC2)
MIPI_CSI_0_N: U3.V14(MIPICSI_0_N) ; port MIPI_CSI_0_N
MIPI_CSI_0_P: U3.W14(MIPICSI_0_P) ; port MIPI_CSI_0_P
MIPI_CSI_1_N: U3.V15(MIPICSI_1_N) ; port MIPI_CSI_1_N
MIPI_CSI_1_P: U3.W15(MIPICSI_1_P) ; port MIPI_CSI_1_P
MIPI_CSI_C_N: U3.V16(MIPICSI_C_N) ; port MIPI_CSI_C_N
MIPI_CSI_C_P: U3.W16(MIPICSI_C_P) ; port MIPI_CSI_C_P
MIPI_DSI_0_N: U3.V11(MIPIDSI_0_N) ; port MIPI_DSI_0_N
MIPI_DSI_0_P: U3.W11(MIPIDSI_0_P) ; port MIPI_DSI_0_P
MIPI_DSI_1_N: U3.V9(MIPIDSI_1_N) ; port MIPI_DSI_1_N
MIPI_DSI_1_P: U3.W9(MIPIDSI_1_P) ; port MIPI_DSI_1_P
MIPI_DSI_C_N: U3.V10(MIPIDSI_C_N) ; port MIPI_DSI_C_N
MIPI_DSI_C_P: U3.W10(MIPIDSI_C_P) ; port MIPI_DSI_C_P
NSRST: U3.J12(NSRST) ; port NSRST
OSPI0_D0: U5.D3(SI(I/O0)) ; port OSPI0_D0
OSPI0_D1: U5.D2(SO(I/O1)) ; port OSPI0_D1
OSPI0_D2: U5.C4(~{WP}_I/O2) ; port OSPI0_D2
OSPI0_D3: U5.D4(I/O3) ; port OSPI0_D3
OSPI0_D4: U5.D5(I/O4) ; port OSPI0_D4
OSPI0_D5: U5.E3(I/O5) ; port OSPI0_D5
OSPI0_D6: U5.E2(I/O6) ; port OSPI0_D6
OSPI0_D7: U5.E1(I/O7) ; port OSPI0_D7
OSPI0_INTn: R30.1 U5.A5(NC_~{INT})
OSPI0_RESETn: U5.A4(~{RESET}) ; port OSPI0_RESETn
OSPI0_RXDS: R35.1 ; port OSPI0_RXDS
OSPI0_SCLK: U5.B2(SCK) ; port OSPI0_SCLK
OSPI0_SCLKN: U5.B1(~{PS_SCK}) ; port OSPI0_SCLKN
OSPI0_SS0: R31.2 R33.2 U5.C2(~{FL_CS}) ; port OSPI0_SS0
OSPI1_D0: U4.D3(SI(I/O0)) ; port OSPI1_D0
OSPI1_D1: U4.D2(SO(I/O1)) ; port OSPI1_D1
OSPI1_D2: U4.C4(~{WP}_I/O2) ; port OSPI1_D2
OSPI1_D3: U4.D4(I/O3) ; port OSPI1_D3
OSPI1_D4: U4.D5(I/O4) ; port OSPI1_D4
OSPI1_D5: U4.E3(I/O5) ; port OSPI1_D5
OSPI1_D6: U4.E2(I/O6) ; port OSPI1_D6
OSPI1_D7: U4.E1(I/O7) ; port OSPI1_D7
OSPI1_INTn: R28.1 U4.A5(NC_~{INT})
OSPI1_RESETn: U4.A4(~{RESET}) ; port OSPI1_RESETn
OSPI1_RXDS: R34.1 ; port OSPI1_RXDS
OSPI1_SCLK: U4.B2(SCK) ; port OSPI1_SCLK
OSPI1_SCLKN: U4.B1(~{PS_SCK}) ; port OSPI1_SCLKN
OSPI1_SS0: R26.2 R32.2 U4.C2(~{FL_CS}) ; port OSPI1_SS0
PMU_AMUX: TP23.1 U3.M18(AMUX_PMU)
POR_N: R39.1 SW1.1(COMMON) U3.U18(POR_N) ; port POR_N
SEUART_RX: U3.A14(SEUART_RX) ; port SEUART_RX
SEUART_TX: U3.A13(SEUART_TX) ; port SEUART_TX
USB_DEV_N: U3.V7(USB_DM) ; port USB_DEV_N
USB_DEV_P: U3.W7(USB_DP) ; port USB_DEV_P
USB_ID: U3.R9(USB_IO_ID) ; port USB_DEV_ID
USB_VB_T: R100.2 R101.1 U3.W6(USB_VBUS)
NetR27_1: R27.1 U4.C5(DNU_~{WP}_~{PSC})
NetR29_1: R29.1 U5.C5(DNU_~{WP}_~{PSC})
NetR32_1: R32.1 U4.A3(~{PS_CS})
NetR33_1: R33.1 U5.A3(~{PS_CS})
NetR34_2: R34.2 U4.C3(RWDS)
NetR35_2: R35.2 U5.C3(RWDS)
NetR36_2: R36.2 U3.V8(USB_REXT)
NetR37_1: R37.1 U3.V13(MIPI_REXT)

Not connected (* = marked no-connect by the designer): U3 C1(nc); U4 A2(NC) B5(DNU_PSC); U5 A2(NC) B5(DNU_PSC)

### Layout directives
differential pair; differential pair class MIPI_CSI_0: MIPI_CSI_0_N, MIPI_CSI_0_P
differential pair; differential pair class MIPI_CSI_1: MIPI_CSI_1_N, MIPI_CSI_1_P
differential pair; differential pair class MIPI_CSI_C: MIPI_CSI_C_N, MIPI_CSI_C_P
differential pair; differential pair class MIPI_DSI_0: MIPI_DSI_0_N, MIPI_DSI_0_P
differential pair; differential pair class MIPI_DSI_1: MIPI_DSI_1_N, MIPI_DSI_1_P
differential pair; differential pair class MIPI_DSI_C: MIPI_DSI_C_N, MIPI_DSI_C_P
differential pair; differential pair class USB_DEV: USB_DEV_N, USB_DEV_P

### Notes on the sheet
- (near R27) DNI for Cypress
- DNI for Cypress Flash
- (near R29) Install only for Flash
- (near R29) DNI
- (near U4) Octal SPI Flash
- "Universal" Octal SPI Devices.  Either chip can be Flash or RAM
- (near U5) Octal SPI Hyper PSRAM
- SEUART
- Crystal Oscillators and Test Pins
- USB, MIPI CSI and DSI Interfaces
- (near SW1) Reset Switch

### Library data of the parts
C37-C42 = Cap: as C9 on sheet 2-PowerInput
R26 R31 R101 = Res3: as R3 on sheet 2-PowerInput
R27 R28 R39 = Res3: as R15 on sheet 2-PowerInput
R29 R30 = Res3: as R6 on sheet 2-PowerInput
R32-R35 = Res3: as R2 on sheet 2-PowerInput
R36 R37 = Res3: Res,200R,1%,100ppm,0402; Manufacturer 1: Stackpol; Manufacturer Part Number 1: RMCF0402FT220R; Wattage: 63mW
R100 = Res3: as R4 on sheet 2-PowerInput
SW1 = SW-SPST: Swit, SPST, Momentary Pushputton, 2 pin, 6.0x3.5mm, H=5.0mm; Manufacturer 1: E-Switch; Manufacturer Part Number 1: TL1107BF180WQ
TP22 TP23 = Hdr_M_1X1_2M54_STRT_UNSHROUD: DNI,Hdr, 0.025" SQ Post Header, Through-hole, Vertical, -55 to 125 degC, 2.54 mm Pitch, 1-Pin, Male, RoHS; Manufacturer: Samtec; Manufacturer Part Number 1: TSW-101-07-L-S; Pitch: 2.54 mm
U3 = E7_B0_194BGA: IC,Alif E7 MCU, Rev B silicon,BGA194; Manufacturer 1: Alif Semi; Manufacturer Part Number 1: AE722F80F55D5LS
U4 = IC_OctalSPI_Generic_1: IC, Flash,64MB x 8, Octal SPI, Ind Temp, 1.8V,24-BGA; Manufacturer 1: ISSI
U5 = IC_OctalSPI_Generic_1: IC, Hyper PSRAM,64MB x 8, Octal SPI, Ind Temp, 1.8V,24-BGA; Manufacturer 1: ISSI
Y1 = Xtal_38M4_20PPM6PF_2016-4P_1: Crystal,38.4MHz,20ppm,6.0pF,100ohm,2016-4pin; Manufacturer 1: Murata; Manufacturer Part Number 1: XRCGB38M400F2P00R0; ESR: 100
Y2 = Xtal_32K768_20PPM6PF_3215-2P_1: Crystal,32.768KHz,20ppm,6.0pF,100ohm,3215-4pin; Manufacturer 1: Abracon; Manufacturer Part Number 1: ABS07-32.768KHZ-6-T; ESR: 70Kohm

## Sheet 5-WiFi.SchDoc: APP KIT BOARD
size 431 x 279 mm; Organization: ORGANIZATION; Address1: ADDRESS 1; Address2: ADDRESS 2; Address3: ADDRESS 3; Address4: ADDRESS 4; DocumentNumber: 5; Revision: -; SheetNumber: 5; SheetTotal: 14; ENG_APP_DATE: --/--/--; DSN_APP_DATE: --/--/--; CHK_APP_DATE: --/--/--
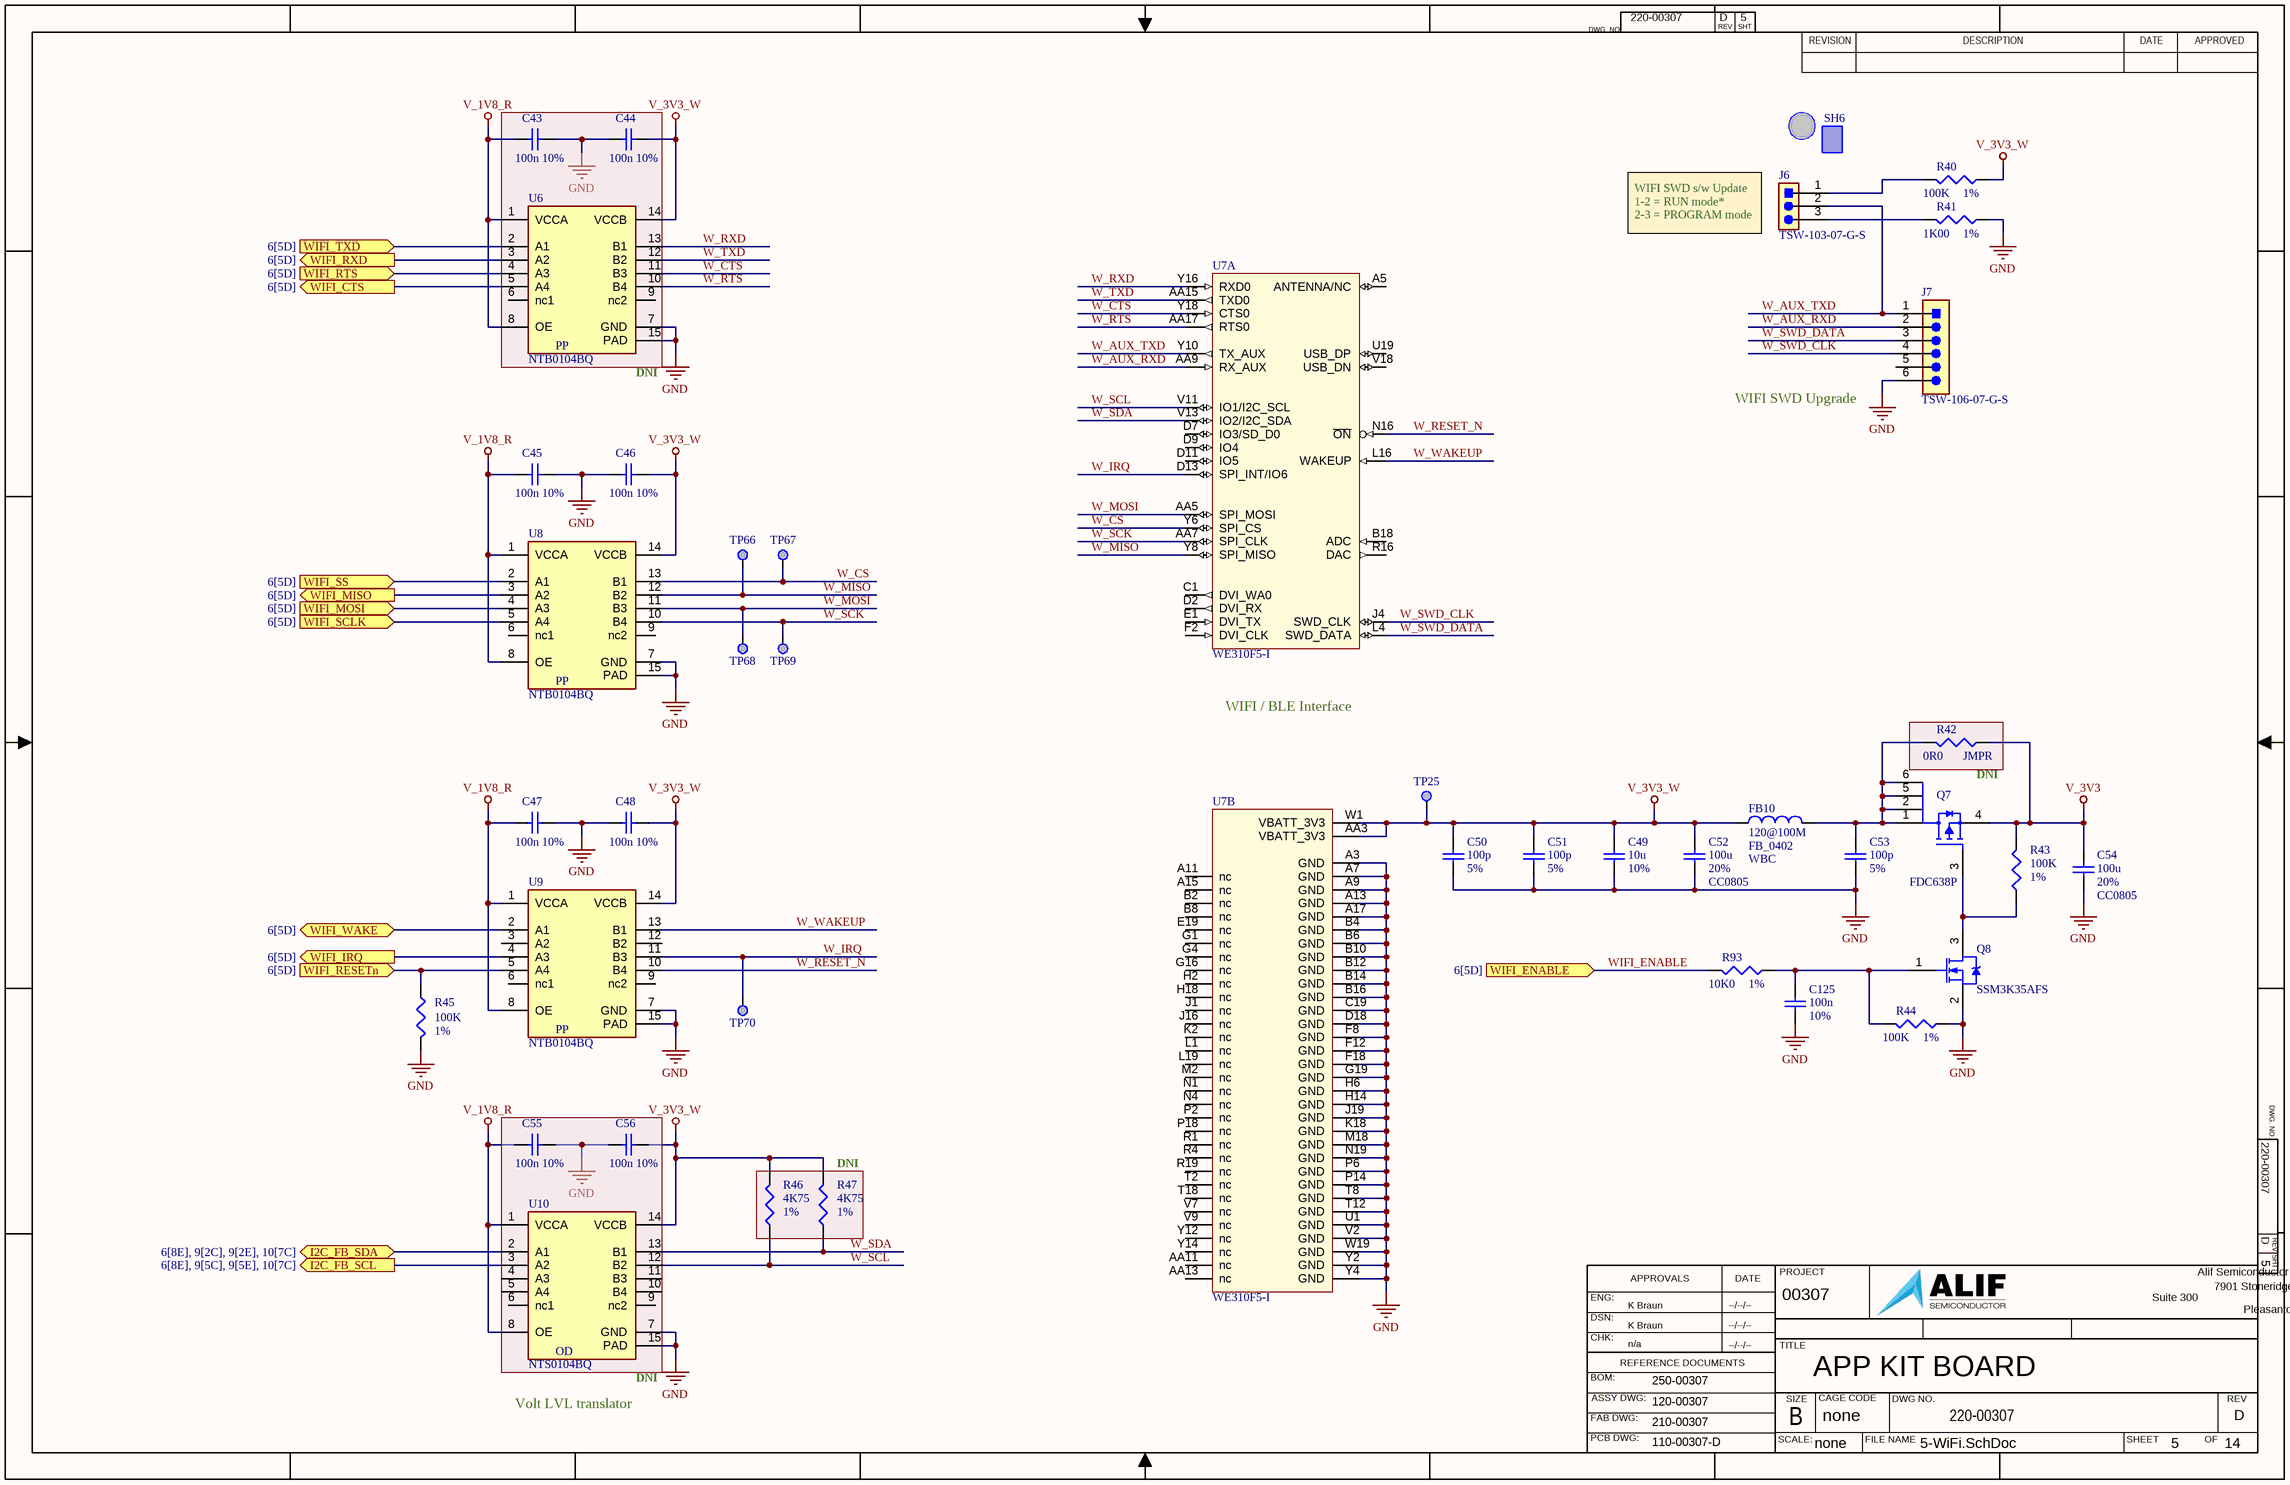
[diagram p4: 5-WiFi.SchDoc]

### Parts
C43  value 100n  Tolerance: 10%  [CAPC0402-01]  (hidden comment: Cap)
C44  value 100n  Tolerance: 10%  [CAPC0402-01]  (hidden comment: Cap)
C45  value 100n  Tolerance: 10%  [CAPC0402-01]  (hidden comment: Cap)
C46  value 100n  Tolerance: 10%  [CAPC0402-01]  (hidden comment: Cap)
C47  value 100n  Tolerance: 10%  [CAPC0402-01]  (hidden comment: Cap)
C48  value 100n  Tolerance: 10%  [CAPC0402-01]  (hidden comment: Cap)
C49  value 10u  Tolerance: 10%  [CAPC0402-01]  (hidden comment: Cap)
C50  value 100p  Tolerance: 5%  [CAPC0402-01]  (hidden comment: Cap)
C51  value 100p  Tolerance: 5%  [CAPC0402-01]  (hidden comment: Cap)
C52  value 100u  PCB_Footprint: CC0805  Tolerance: 20%  [CAPC0805-01]  (hidden comment: Cap)
C53  value 100p  Tolerance: 5%  [CAPC0402-01]  (hidden comment: Cap)
C54  value 100u  PCB_Footprint: CC0805  Tolerance: 20%  [CAPC0805-01]  (hidden comment: Cap)
C55  value 100n  Tolerance: 10%  [CAPC0402-01]  (hidden comment: Cap)
C56  value 100n  Tolerance: 10%  [CAPC0402-01]  (hidden comment: Cap)
C125  value 100n  Tolerance: 10%  [CAPC0402-01]  (hidden comment: Cap)
FB10  value WBC  Impedance: 120@100M  [FB_0402]  (hidden comment: Inductor)
J6  TSW-103-07-G-S  [CONN_HDR_1X3_STRT_0.100]
J7  TSW-106-07-G-S  [CONN_SAMTEC_TSW-106-07-G-S]
Q7  FDC638P  [SSOT-6]
Q8  Manufacturer Part Number 1: SSM3K35AFS  [SC75_SSM_TOS-L]  (hidden comment: NMOS-2_SOT)
R40  value 100K  Tolerance: 1%  [RESC0402-01]  (hidden comment: Res3)
R41  value 1K00  Tolerance: 1%  [RESC0402-01]  (hidden comment: Res3)
R42  value 0R0  Tolerance: JMPR  [RESC0402-01]  (hidden comment: Res3)
R43  value 100K  Tolerance: 1%  [RESC0402-01]  (hidden comment: Res3)
R44  value 100K  Tolerance: 1%  [RESC0402-01]  (hidden comment: Res3)
R45  value 100K  Tolerance: 1%  [RESC0402-01]  (hidden comment: Res3)
R46  value 4K75  Tolerance: 1%  [RESC0402-01]  (hidden comment: Res3)
R47  value 4K75  Tolerance: 1%  [RESC0402-01]  (hidden comment: Res3)
R93  value 10K0  Tolerance: 1%  [RESC0402-01]  (hidden comment: Res3)
SH6  Shunt  (value not drawn)  (mechanical)
TP25  TP_SMPAD  [TP_30_RND]  (value not drawn)  (no BOM)
TP66  TP_SMPAD  [TP_30_RND]  (value not drawn)  (no BOM)
TP67  TP_SMPAD  [TP_30_RND]  (value not drawn)  (no BOM)
TP68  TP_SMPAD  [TP_30_RND]  (value not drawn)  (no BOM)
TP69  TP_SMPAD  [TP_30_RND]  (value not drawn)  (no BOM)
TP70  TP_SMPAD  [TP_30_RND]  (value not drawn)  (no BOM)
U6  NTB0104BQ  [DHVQFN-14(2.5x3.0)_NXP]
U7  WE310F5-I  [MODULE_TELIT_WE310F5-I_ME310G1]  (parts A,B of 2)
U8  NTB0104BQ  [DHVQFN-14(2.5x3.0)_NXP]
U9  NTB0104BQ  [DHVQFN-14(2.5x3.0)_NXP]
U10  NTS0104BQ  [DHVQFN-14(2.5x3.0)_NXP]

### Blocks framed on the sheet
DNI: R46 R47

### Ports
I2C_FB_SCL (out, see 6[8E], 9[5C], 9[5E], 10[7C]), I2C_FB_SDA (bidir, see 6[8E], 9[2C], 9[2E], 10[7C]), WIFI_CTS (out, see 6[5D]), WIFI_ENABLE (in, see 6[5D]), WIFI_IRQ (out, see 6[5D]), WIFI_MISO (out, see 6[5D]), WIFI_MOSI (in, see 6[5D]), WIFI_RESETn (in, see 6[5D]), WIFI_RTS (in, see 6[5D]), WIFI_RXD (out, see 6[5D]), WIFI_SCLK (in, see 6[5D]), WIFI_SS (in, see 6[5D]), WIFI_TXD (in, see 6[5D]), WIFI_WAKE (bidir, see 6[5D])

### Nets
GND: C43.1 C44.2 C45.1 C46.2 C47.1 C48.2 C49.1 C50.1 C51.1 C52.1 C53.1 C54.1 C55.1 C56.2 C125.1 J7.6 Q8.2(S) R41.1 R44.1 R45.2 U6.7(GND) U6.15(PAD) U7.A3(GND) U7.A7(GND) U7.A9(GND) U7.A13(GND) U7.A17(GND) U7.B4(GND) U7.B6(GND) U7.B10(GND) U7.B12(GND) U7.B14(GND) U7.B16(GND) U7.C19(GND) U7.D18(GND) U7.F8(GND) U7.F12(GND) U7.F18(GND) U7.G19(GND) U7.H6(GND) U7.H14(GND) U7.J19(GND) U7.K18(GND) U7.M18(GND) U7.N19(GND) U7.P6(GND) U7.P14(GND) U7.T8(GND) U7.T12(GND) U7.U1(GND) U7.V2(GND) U7.W19(GND) U7.Y2(GND) U7.Y4(GND) U8.7(GND) U8.15(PAD) U9.7(GND) U9.15(PAD) U10.7(GND) U10.15(PAD)
V_1V8_R: C43.2 C45.2 C47.2 C55.2 U6.1(VCCA) U6.8(OE) U8.1(VCCA) U8.8(OE) U9.1(VCCA) U9.8(OE) U10.1(VCCA) U10.8(OE)
V_3V3: C54.2 Q7.4(S) R42.1 R43.2
V_3V3_W: C44.1 C46.1 C48.1 C49.2 C50.2 C51.2 C52.2 C56.1 FB10.2 R40.1 R46.2 R47.2 TP25.1 U6.14(VCCB) U7.AA3(VBATT_3V3) U7.W1(VBATT_3V3) U8.14(VCCB) U9.14(VCCB) U10.14(VCCB)
I2C_FB_SCL: U10.3(A2) ; port I2C_FB_SCL
I2C_FB_SDA: U10.2(A1) ; port I2C_FB_SDA
P0_4: U6.3(A2) ; port WIFI_RXD
P0_5: U6.2(A1) ; port WIFI_TXD
P0_6: U6.5(A4) ; port WIFI_CTS
P0_7: U6.4(A3) ; port WIFI_RTS
P12_4: U8.3(A2) ; port WIFI_MISO
P12_5: U8.4(A3) ; port WIFI_MOSI
P12_6: U8.5(A4) ; port WIFI_SCLK
P12_7: U8.2(A1) ; port WIFI_SS
P13_1: U9.2(A1) ; port WIFI_WAKE
P13_2: R45.1 U9.5(A4) ; port WIFI_RESETn
P13_3: U9.4(A3) ; port WIFI_IRQ
W_AUX_RXD: J7.2 U7.AA9(RX_AUX)
W_AUX_TXD: J6.2 J7.1 U7.Y10(TX_AUX)
W_CS: TP67.1 U7.Y6(SPI_CS) U8.13(B1)
W_CTS: U6.11(B3) U7.Y18(CTS0)
W_IRQ: TP70.1 U7.D13(SPI_INT/IO6) U9.11(B3)
W_MISO: TP66.1 U7.Y8(SPI_MISO) U8.12(B2)
W_MOSI: TP68.1 U7.AA5(SPI_MOSI) U8.11(B3)
W_RESET_N: U7.N16(~{ON}) U9.10(B4)
W_RTS: U6.10(B4) U7.AA17(RTS0)
W_RXD: U6.13(B1) U7.Y16(RXD0)
W_SCK: TP69.1 U7.AA7(SPI_CLK) U8.10(B4)
W_SCL: R46.1 U7.V11(IO1/I2C_SCL) U10.12(B2)
W_SDA: R47.1 U7.V13(IO2/I2C_SDA) U10.13(B1)
W_SWD_CLK: J7.4 U7.J4(SWD_CLK)
W_SWD_DATA: J7.3 U7.L4(SWD_DATA)
W_TXD: U6.12(B2) U7.AA15(TXD0)
W_WAKEUP: U7.L16(WAKEUP) U9.13(B1)
WIFI_ENABLE: R93.2 ; port WIFI_ENABLE  [project net P13_0]
NetC53_2: C53.2 FB10.1 Q7.1(D) Q7.2(D) Q7.5(D) Q7.6(D) R42.2
NetC125_2: C125.2 Q8.1(G) R44.2 R93.1
NetJ6_1: J6.1 R40.2
NetJ6_3: J6.3 R41.2
NetQ7_3: Q7.3(G) Q8.3(D) R43.1

Not connected (* = marked no-connect by the designer): J7 5; U6 6(nc1) 9(nc2); U7 A5(ANTENNA/NC) A11(nc) A15(nc) AA11(nc) AA13(nc) B2(nc) B8(nc) B18(ADC) C1(DVI_WA0) D2(DVI_RX) D7(IO3/SD_D0) D9(IO4) D11(IO5) E1(DVI_TX) E19(nc) F2(DVI_CLK) G1(nc) G4(nc) G16(nc) H2(nc) H18(nc) J1(nc) J16(nc) K2(nc) L1(nc) L19(nc) M2(nc) N1(nc) N4(nc) P2(nc) P18(nc) R1(nc) R4(nc) R16(DAC) R19(nc) T2(nc) T18(nc) U19(USB_DP) V7(nc) V9(nc) V18(USB_DN) Y12(nc) Y14(nc); U8 6(nc1) 9(nc2); U9 3(A2) 6(nc1) 9(nc2) 12(B2); U10 4(A3) 5(A4) 6(nc1) 9(nc2) 10(B4) 11(B3)

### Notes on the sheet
- (near J6) WIFI SWD s/w Update
  1-2 = RUN mode*
  2-3 = PROGRAM mode
- (near U6) DNI
- WIFI SWD Upgrade
- WIFI / BLE Interface
- (near Q7) DNI
- (near U10) Volt LVL translator
- (near U10) DNI

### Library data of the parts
C43 C44 C55 C56 = Cap: as C24 on sheet 3-CPUPower
C45-C48 C125 = Cap: as C9 on sheet 2-PowerInput
C49 = Cap: as C2 on sheet 2-PowerInput
C50 C51 C53 = Cap: Cap,100pF,5%,25V,C0G,Hi-Q,0402; Manufacturer 1: Kemet; Manufacturer Part Number 1: CBR04C101J3GAC; PCB_Footprint: CC0402
C52 C54 = Cap: Cap,100uF,20%,6.3V,X5R,0805; Manufacturer 1: MuRata; Manufacturer Part Number 1: GRM21BR60J107ME15K; Voltage: 6V3
FB10 = Inductor: as FB1 on sheet 2-PowerInput
J6 = Hdr_M_1X3_2M54_STRT_UNSHROUD: as J5 on sheet 3-CPUPower
J7 = Hdr_M_1X6_2M54_STRT_UNSHROUD: Hdr, 0.025" SQ Post Header, Through-hole, Vertical, -55 to 125 degC, 2.54 mm Pitch, 5-Pin, Male, RoHS; Manufacturer: Samtec; Pitch: 2.54 mm
Q7 = FET_PMOS_6P: MOSFET,P-CH,20V,4.5A,48mOhm,SSOT-6; Manufacturer 1: OnSemi; Manufacturer Part Number 1: FDC658P; Manufacturer: ON Semiconductor; Pulse Drain Current: -20A; Drain To Source Breakdown Voltage: -20V; Drain To Source Voltage: -30V; Continuous Drain Current: -4.5A; Turn On Delay Time: 12ns; Input Capacitace At Vds: 750pF @ -15V; Max Forward Diode Voltage: -1.2V; Depletion Mode: False; Number Of Channels: 1; Standoff Height: 0mm; Typ Forward Diode Voltage: -0.76V; Drain To Source Resistance: 0.041Ω; Power Dissipation: 0.8W; Rthja Max: 78°C/W; Turn Off Delay Time: 24ns; Threshold Vgs Max: -3V; Transconductance: 9S; Max Junction Temp: +150°C; Threshold Vgs Min: -1V; Gate Charge At Vgs: 8nC @ -5V
Q8 = NMOS-2_SOT: as Q1 on sheet 2-PowerInput
R40 R43-R45 = Res3: as R15 on sheet 2-PowerInput
R41 = Res3: as R14 on sheet 2-PowerInput
R42 = Res3: as R95 on sheet 2-PowerInput
R46 R47 = Res3: DNI,Res,4K75,1%,100ppm,0402; Manufacturer 1: Stackpol; Manufacturer Part Number 1: RMCF0402FT4K75; Wattage: 63mW
R93 = Res3: as R3 on sheet 2-PowerInput
SH6 = SHUNT_F_1x2_2.5MM_STRT: as SH3 on sheet 3-CPUPower
TP25 TP66-TP70 = TP_SMPAD: as TP1 on sheet 2-PowerInput
U6 = IC_XLAT_NTB0104BQ: DNI,IC, Voltage Level Translator, 4-bit,push-pull,50Mbps,VCC(A): 1.2 V to 3.6 V and VCC(B): 1.65 V to 5.5 V,auto-sense,DHVQFN14(2.5x3.0); Manufacturer_Name: NXP; Manufacturer_Part_Number: NTB0104BQ-Q100X
U7 = MOD_WE310F5-I: Module, WIFI (802.11 b/g/n) / BLE (5.0) MODULE, SMD-94P; Manufacturer 1: Telit; Manufacturer Part Number 1: WE310F5I396R001000; CompType: IC; Operating_Temp: -40C TO +85C
U8 U9 = IC_XLAT_NTB0104BQ: IC, Voltage Level Translator, 4-bit,push-pull,50Mbps,VCC(A): 1.2 V to 3.6 V and VCC(B): 1.65 V to 5.5 V,auto-sense,DHVQFN14(2.5x3.0); Manufacturer_Name: NXP; Manufacturer_Part_Number: NTB0104BQ-Q100X
U10 = IC_XLAT_NTS0104BQ: DNI,IC, Voltage Level Translator, 4-bit,open-drain,50Mbps,VCC(A): 1.2 V to 3.6 V and VCC(B): 1.65 V to 5.5 V,auto-sense,DHVQFN14(2.5x3.0); Manufacturer_Name: NXP; Manufacturer_Part_Number: NTB0104BQ-Q100X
